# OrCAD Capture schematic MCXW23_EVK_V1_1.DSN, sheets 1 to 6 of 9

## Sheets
1 01_Block diagram: size A3; title: MCXW23-EVK-BB; rev: 1.1; company: NXP Semiconductors; note: MCXW23-EVK-BB; note: 6501 William Cannon Drive West; note: Austin, TX 78735-8598
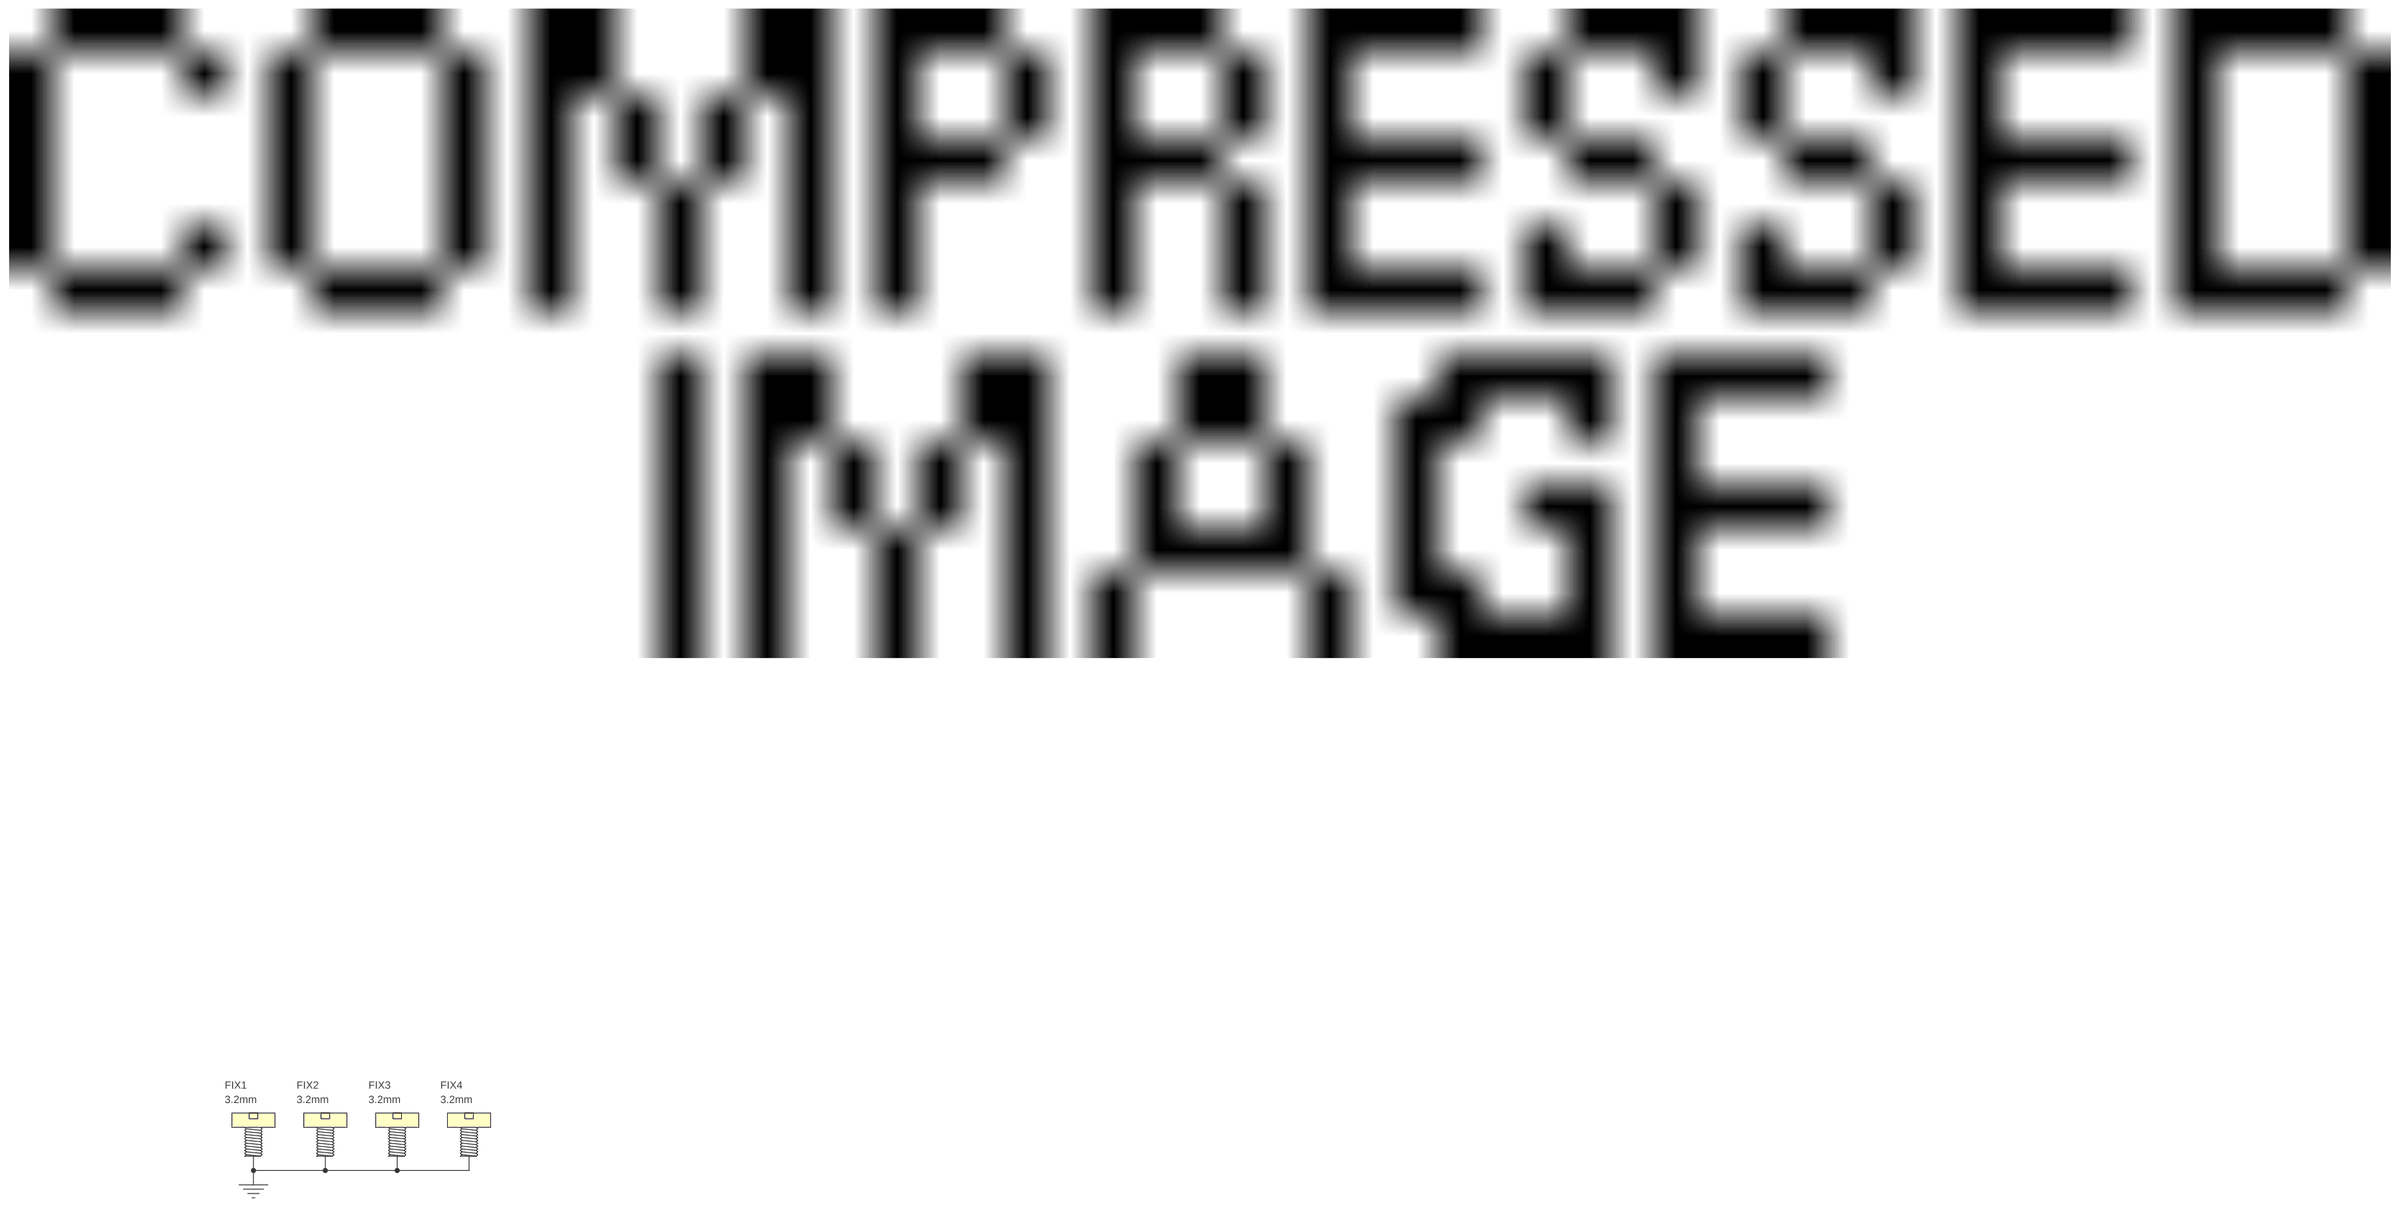
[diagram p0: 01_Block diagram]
2 02_MCXW23xx_RDM: size A3
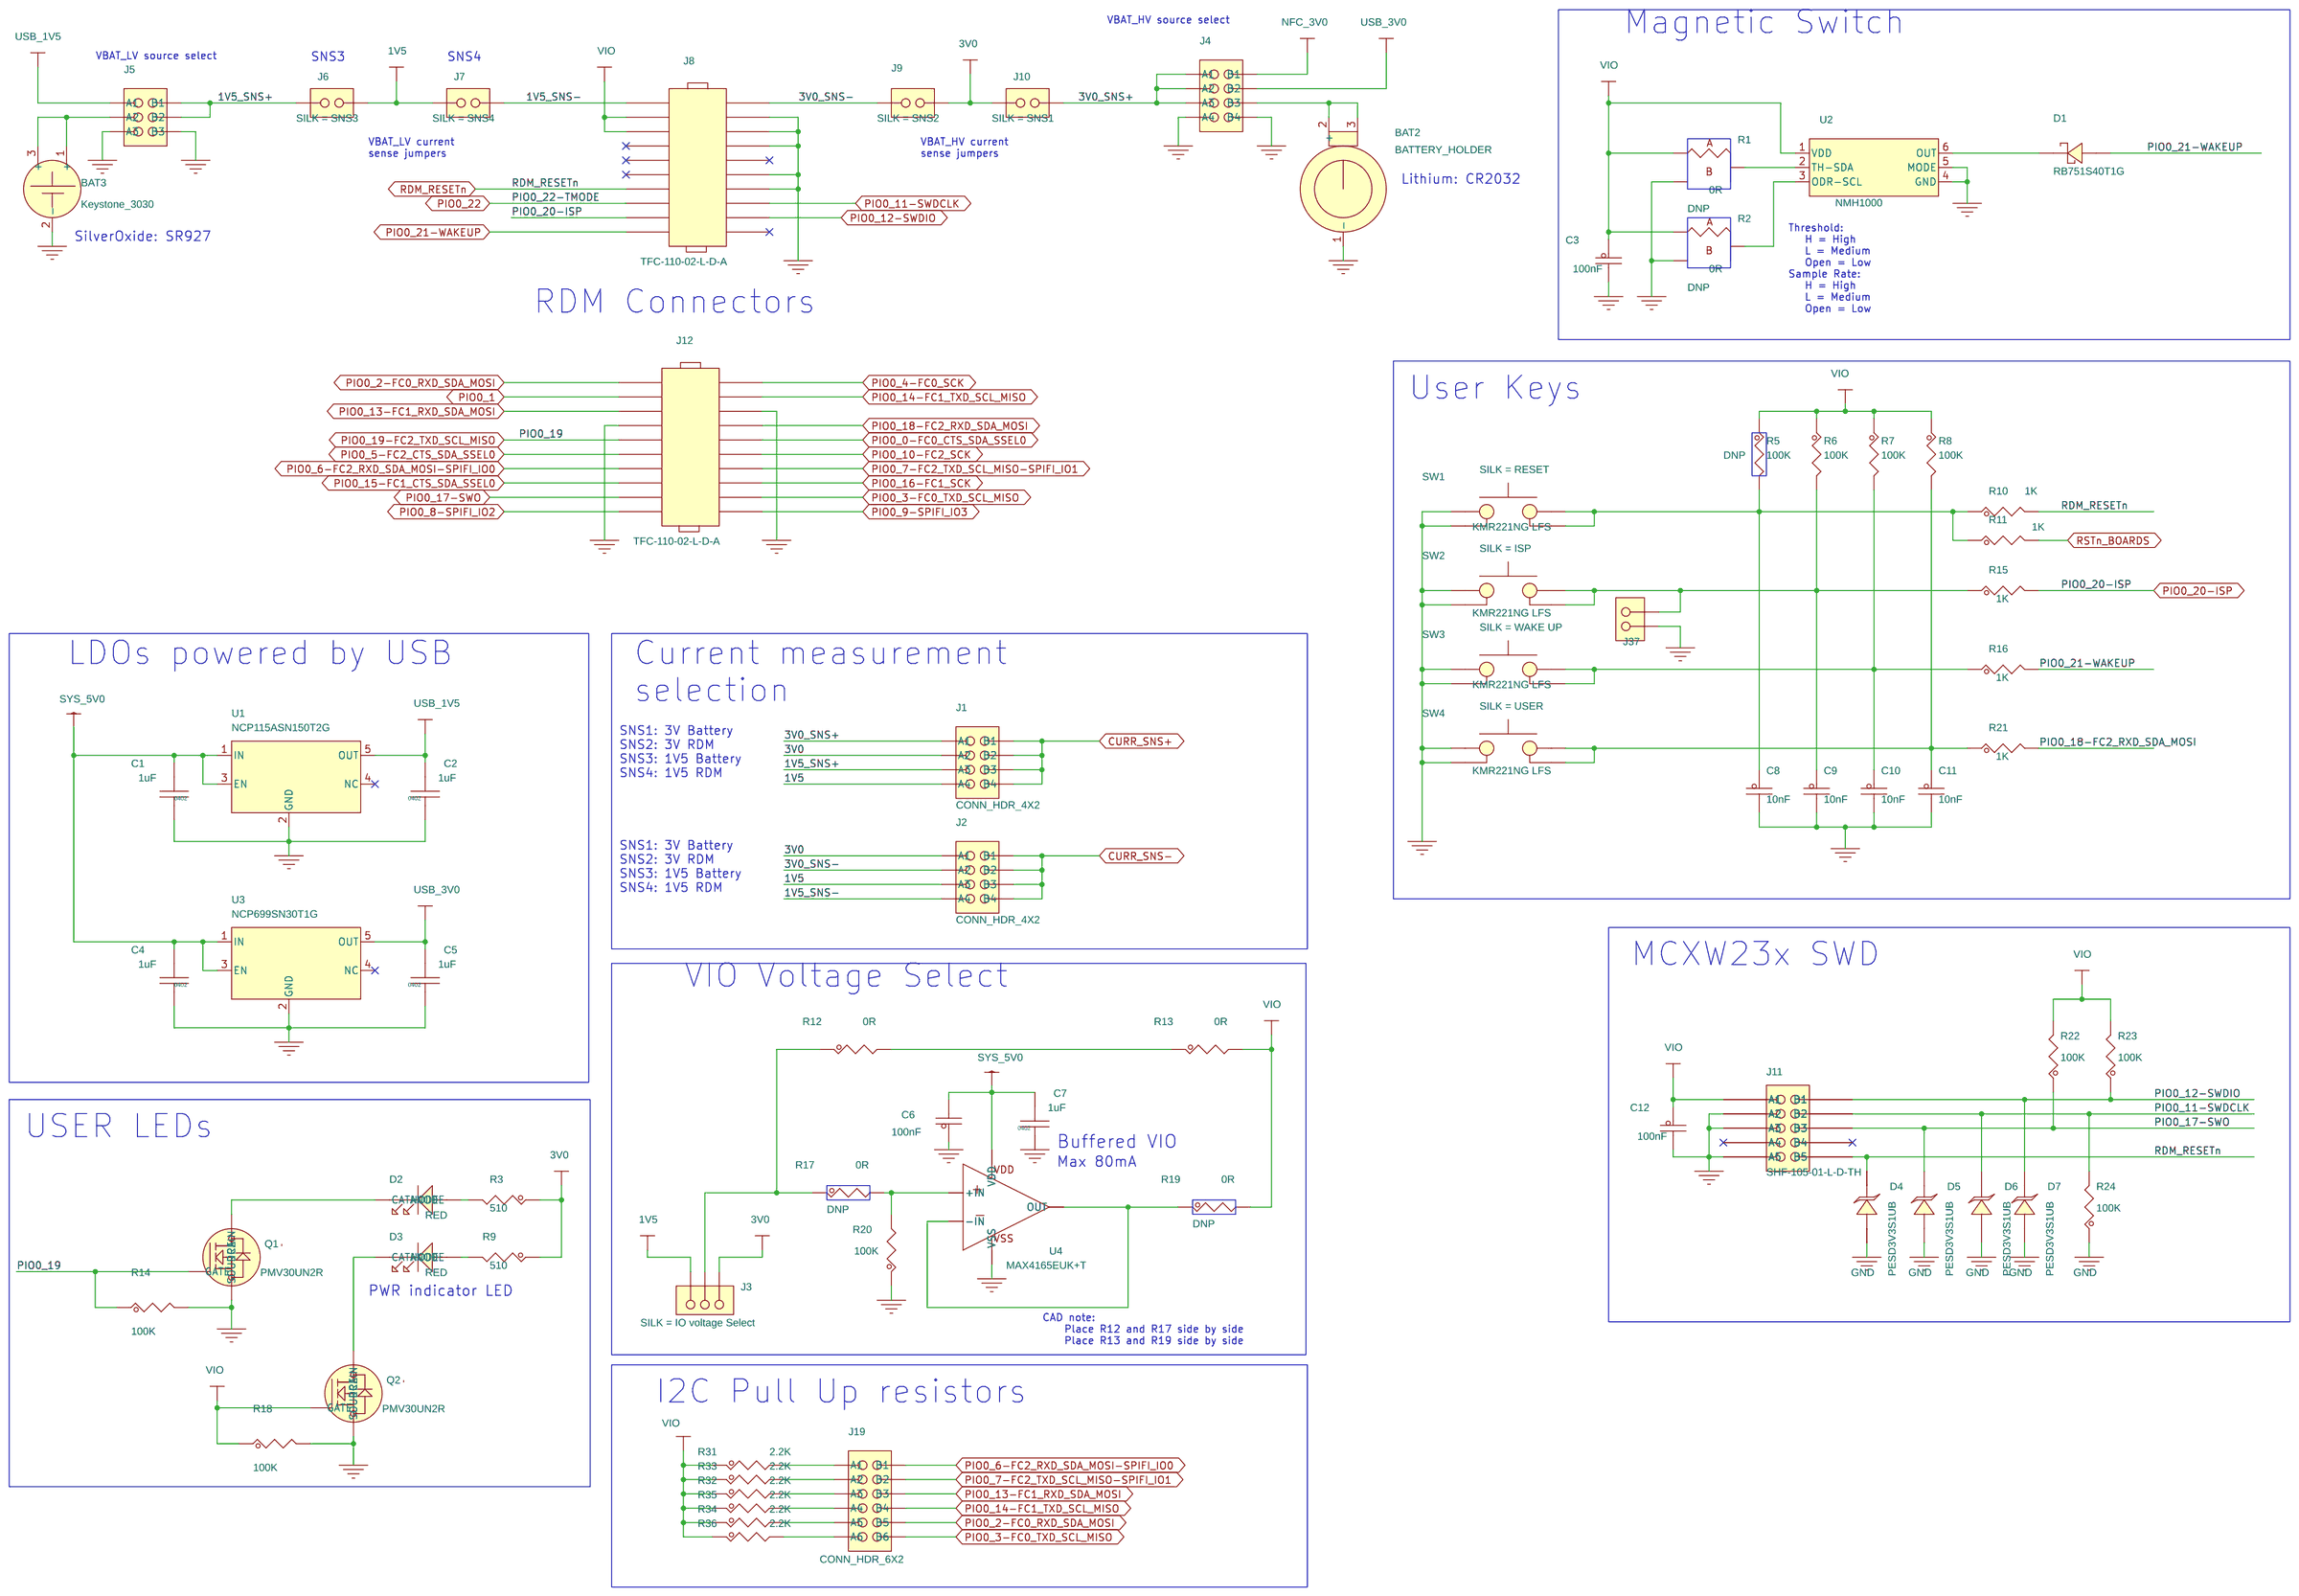
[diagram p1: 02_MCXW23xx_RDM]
3 03_Sensors: size A3
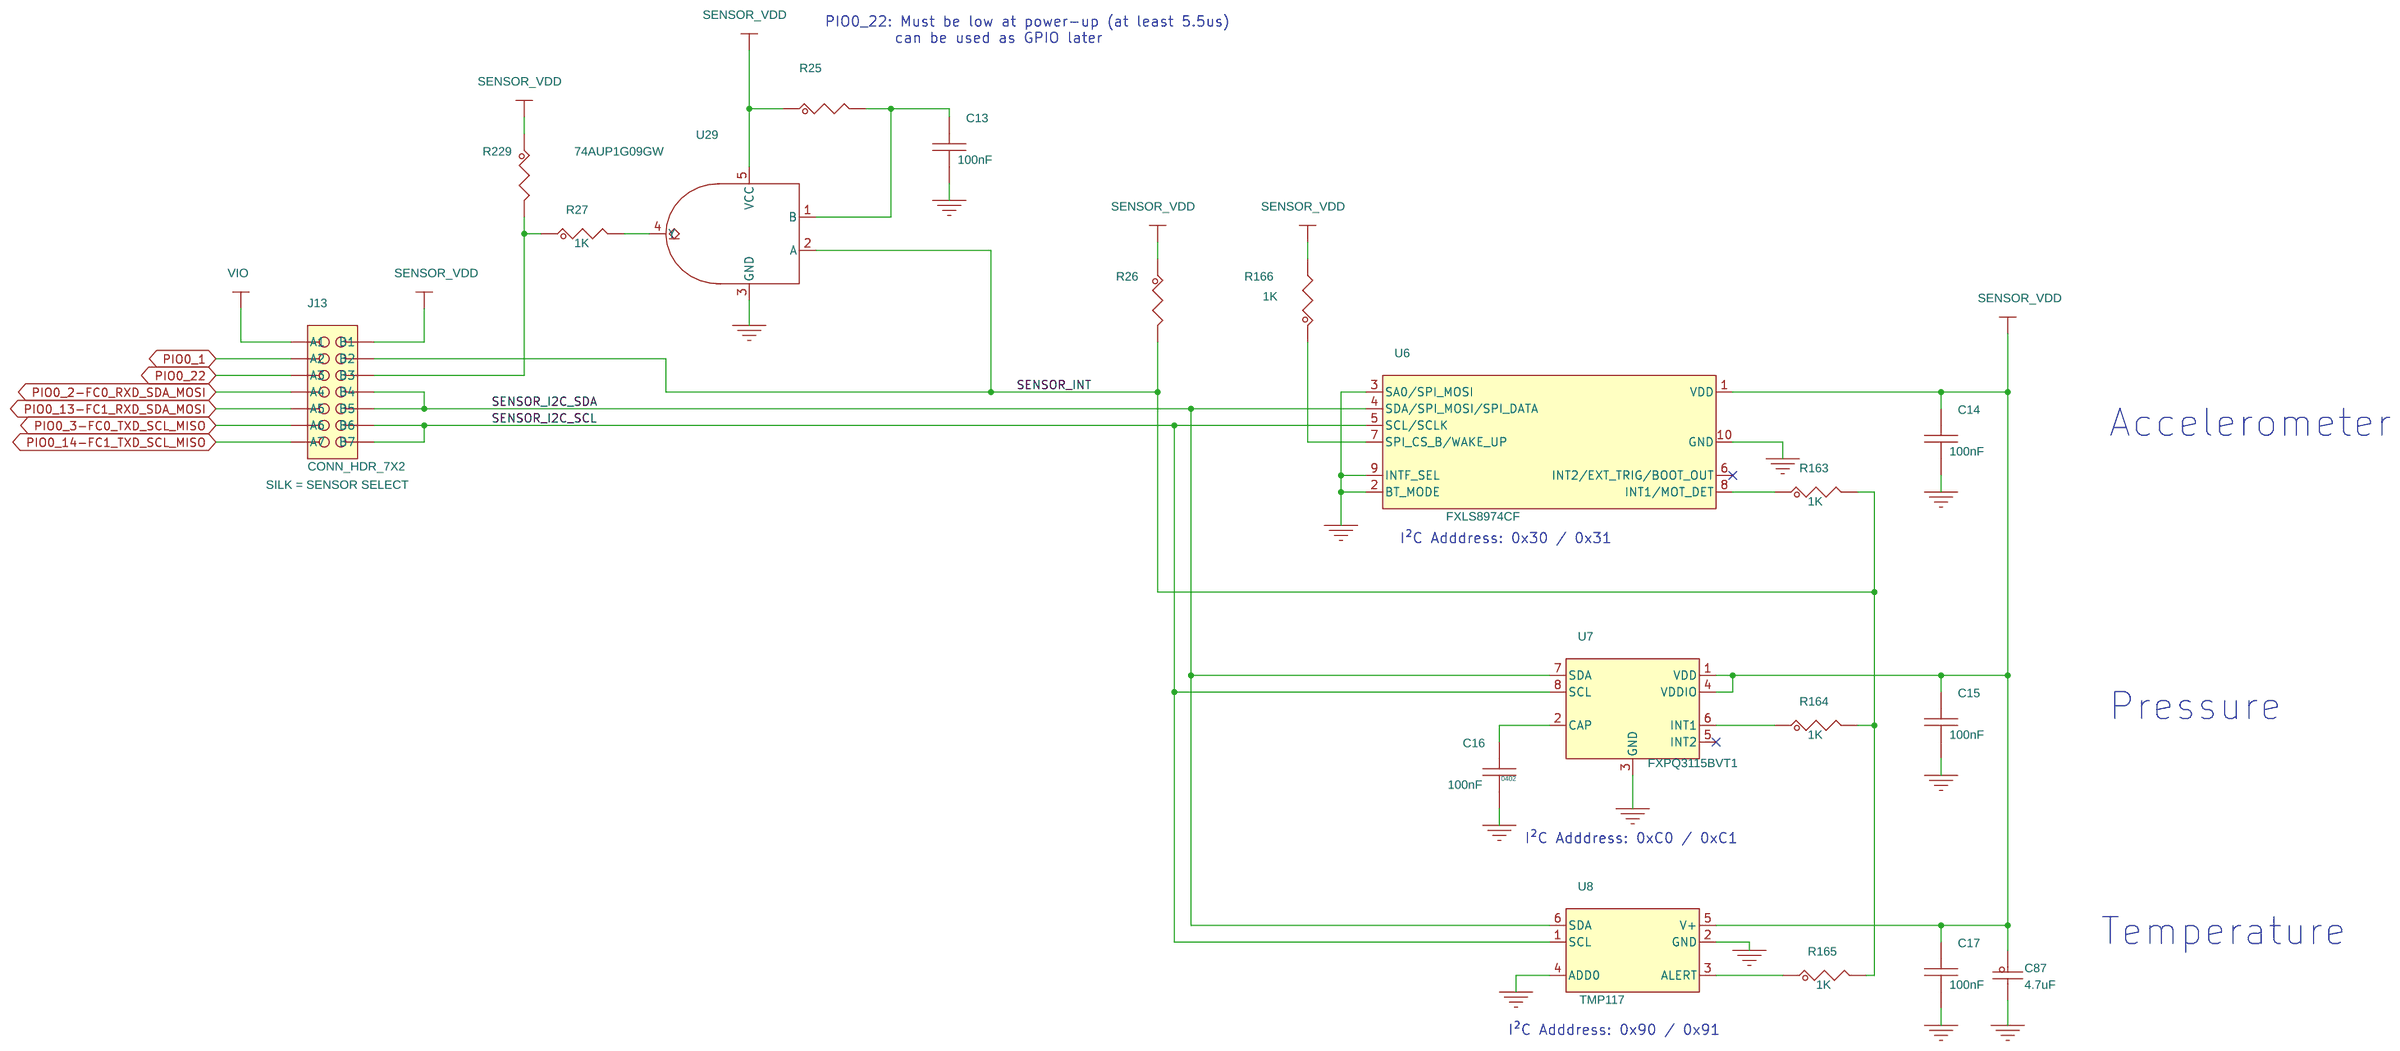
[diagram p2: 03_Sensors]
4 04_MIKRObus_Arduino: size A3
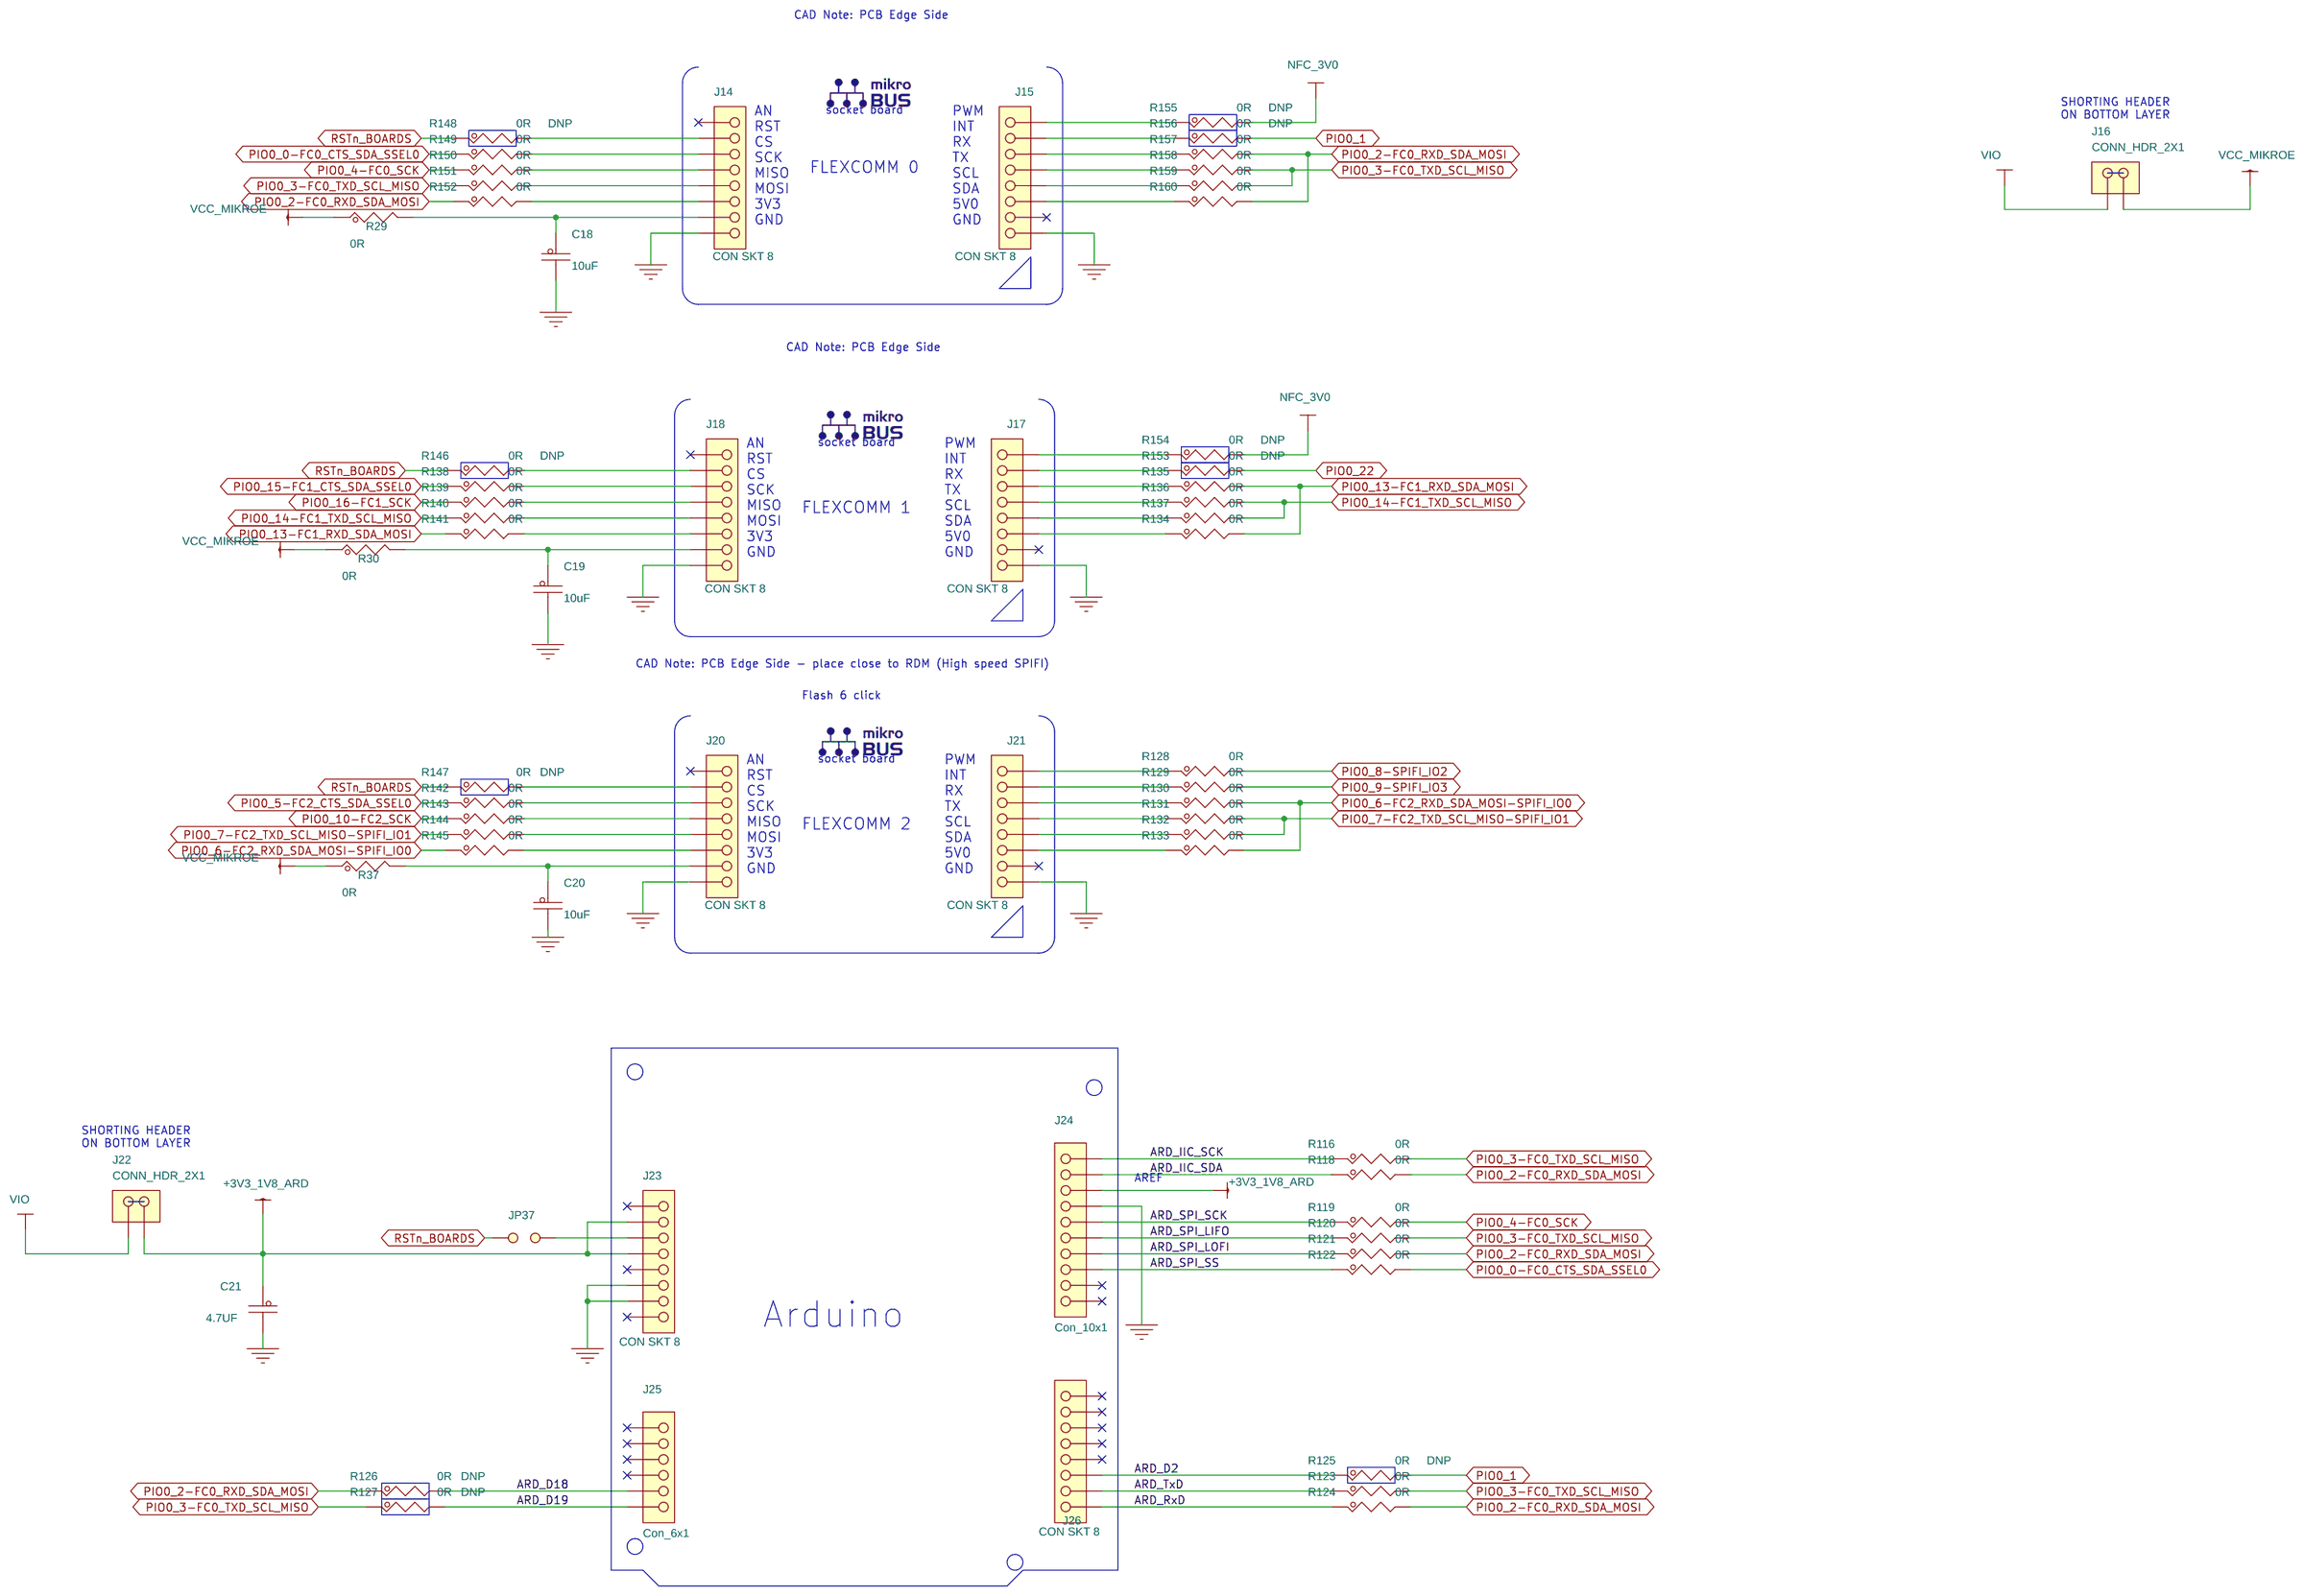
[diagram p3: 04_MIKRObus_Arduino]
5 05_MCU_Link_IO: size A3
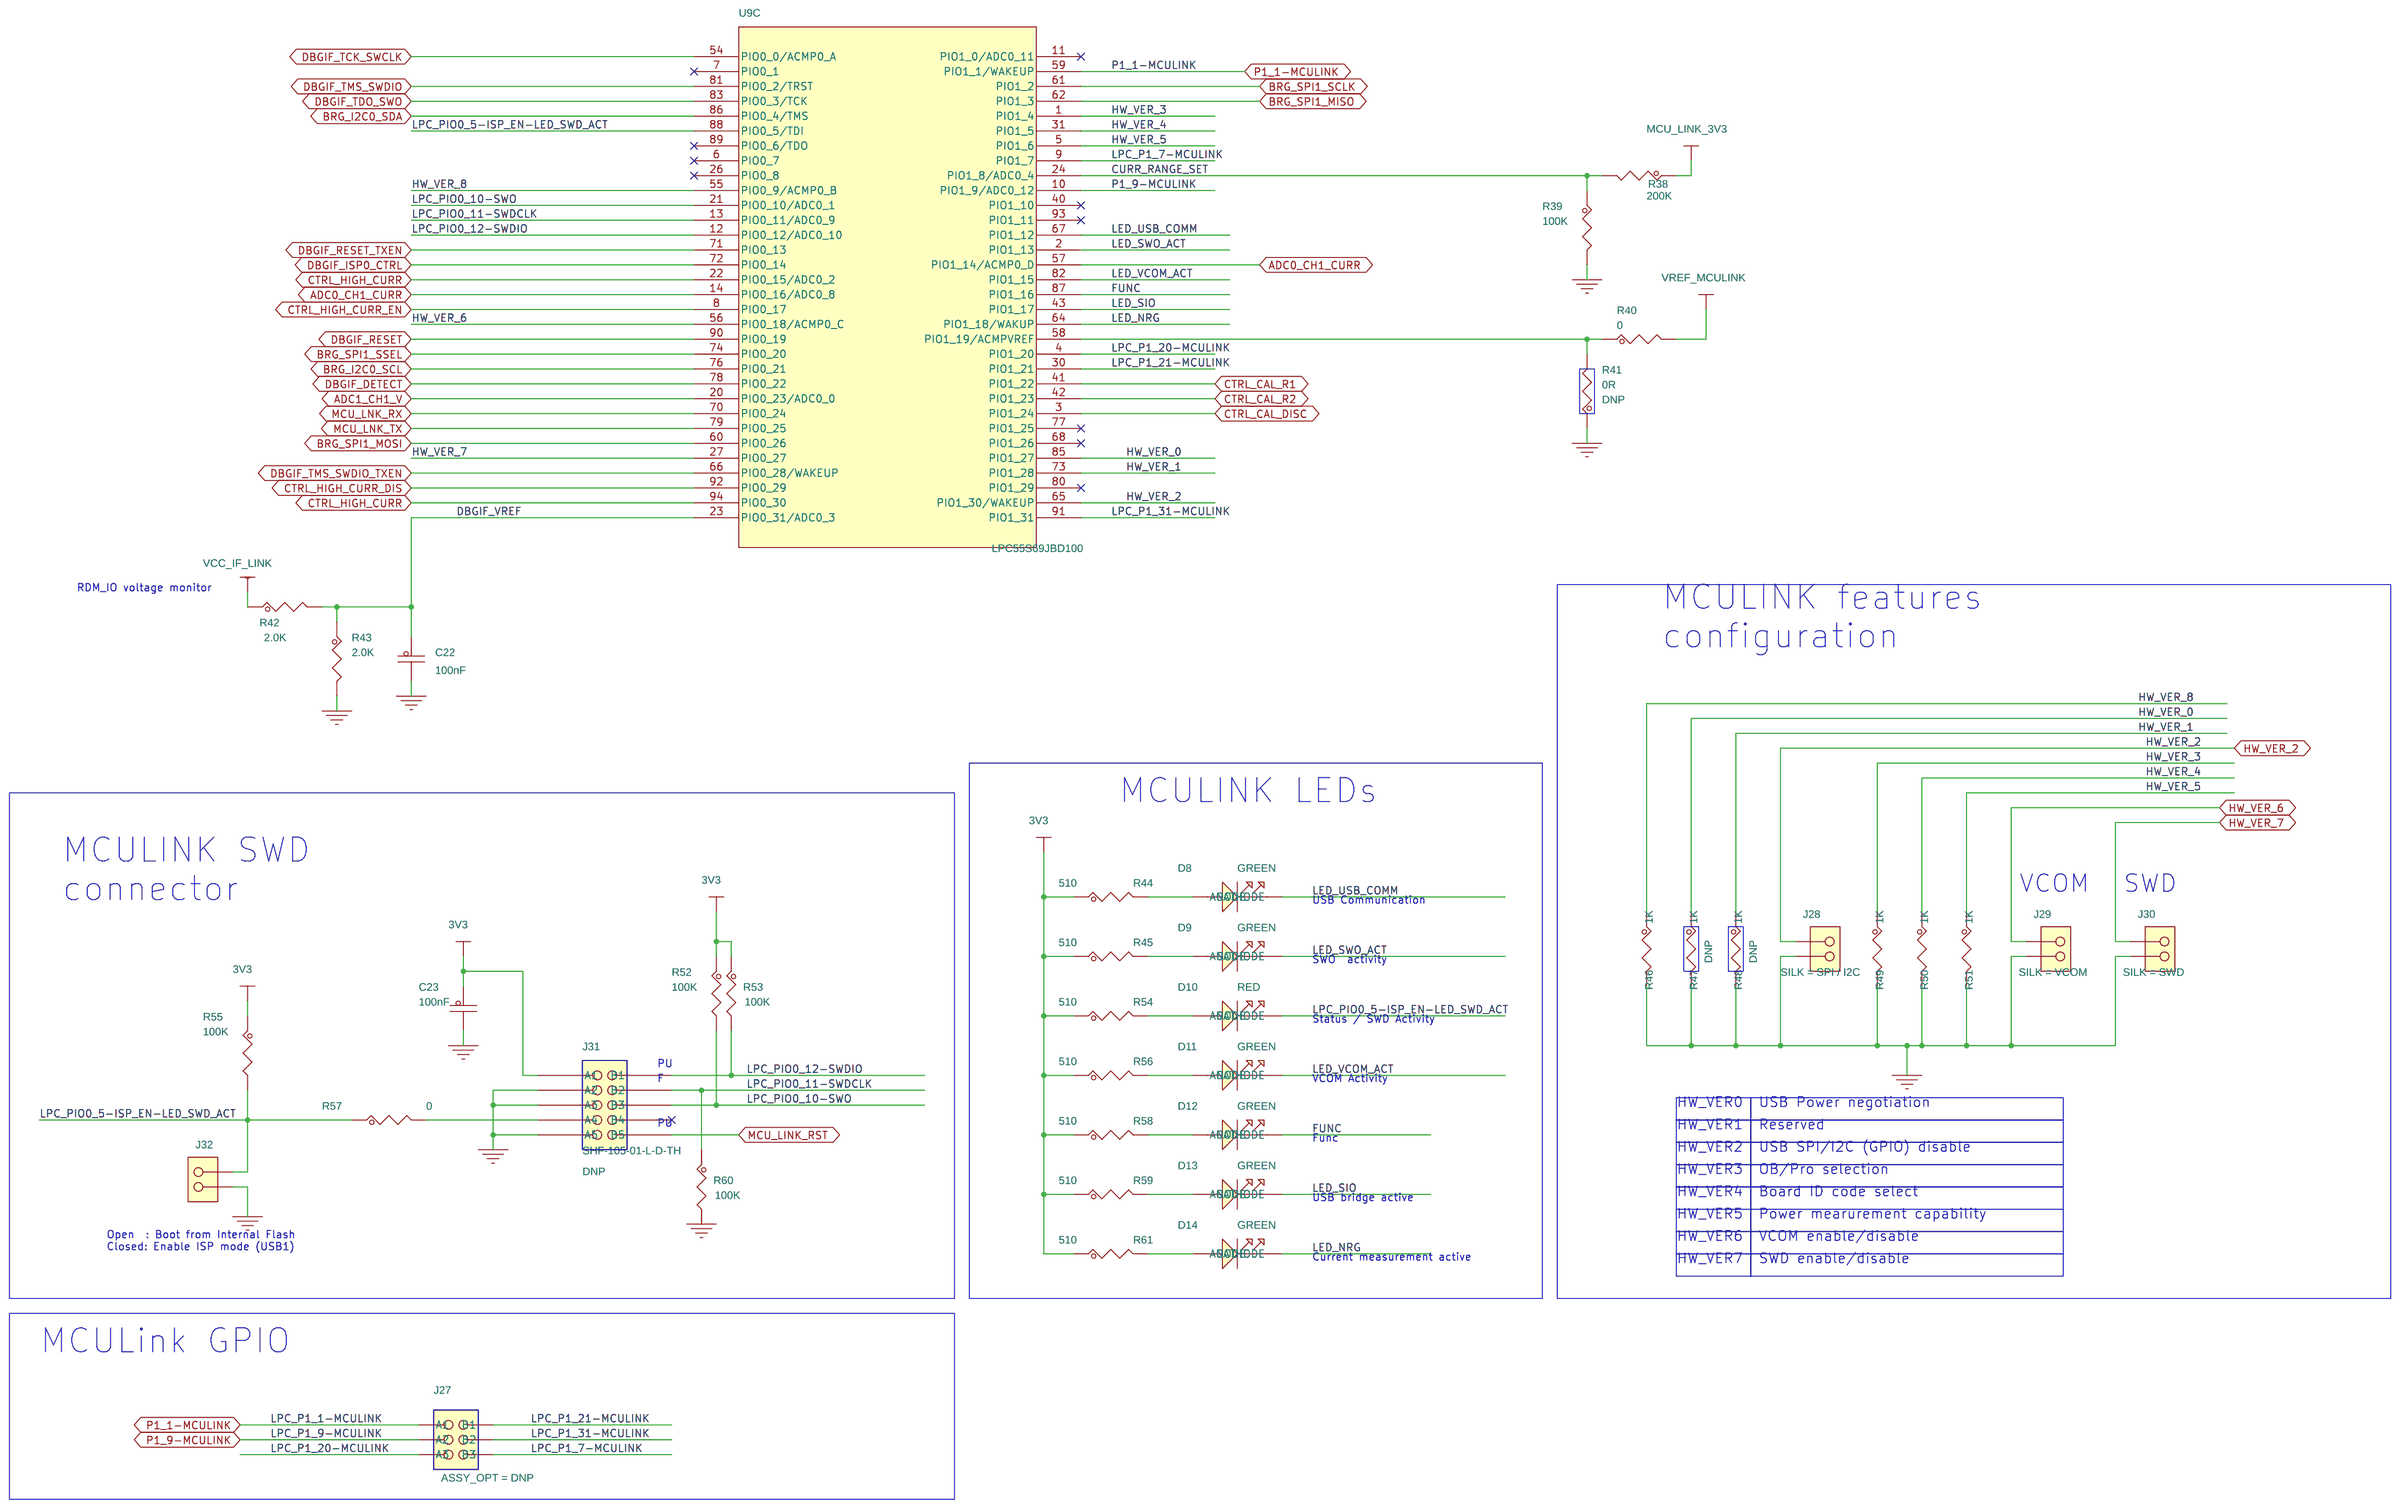
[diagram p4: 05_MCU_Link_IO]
6 06_MCU_link_PWR: size A3
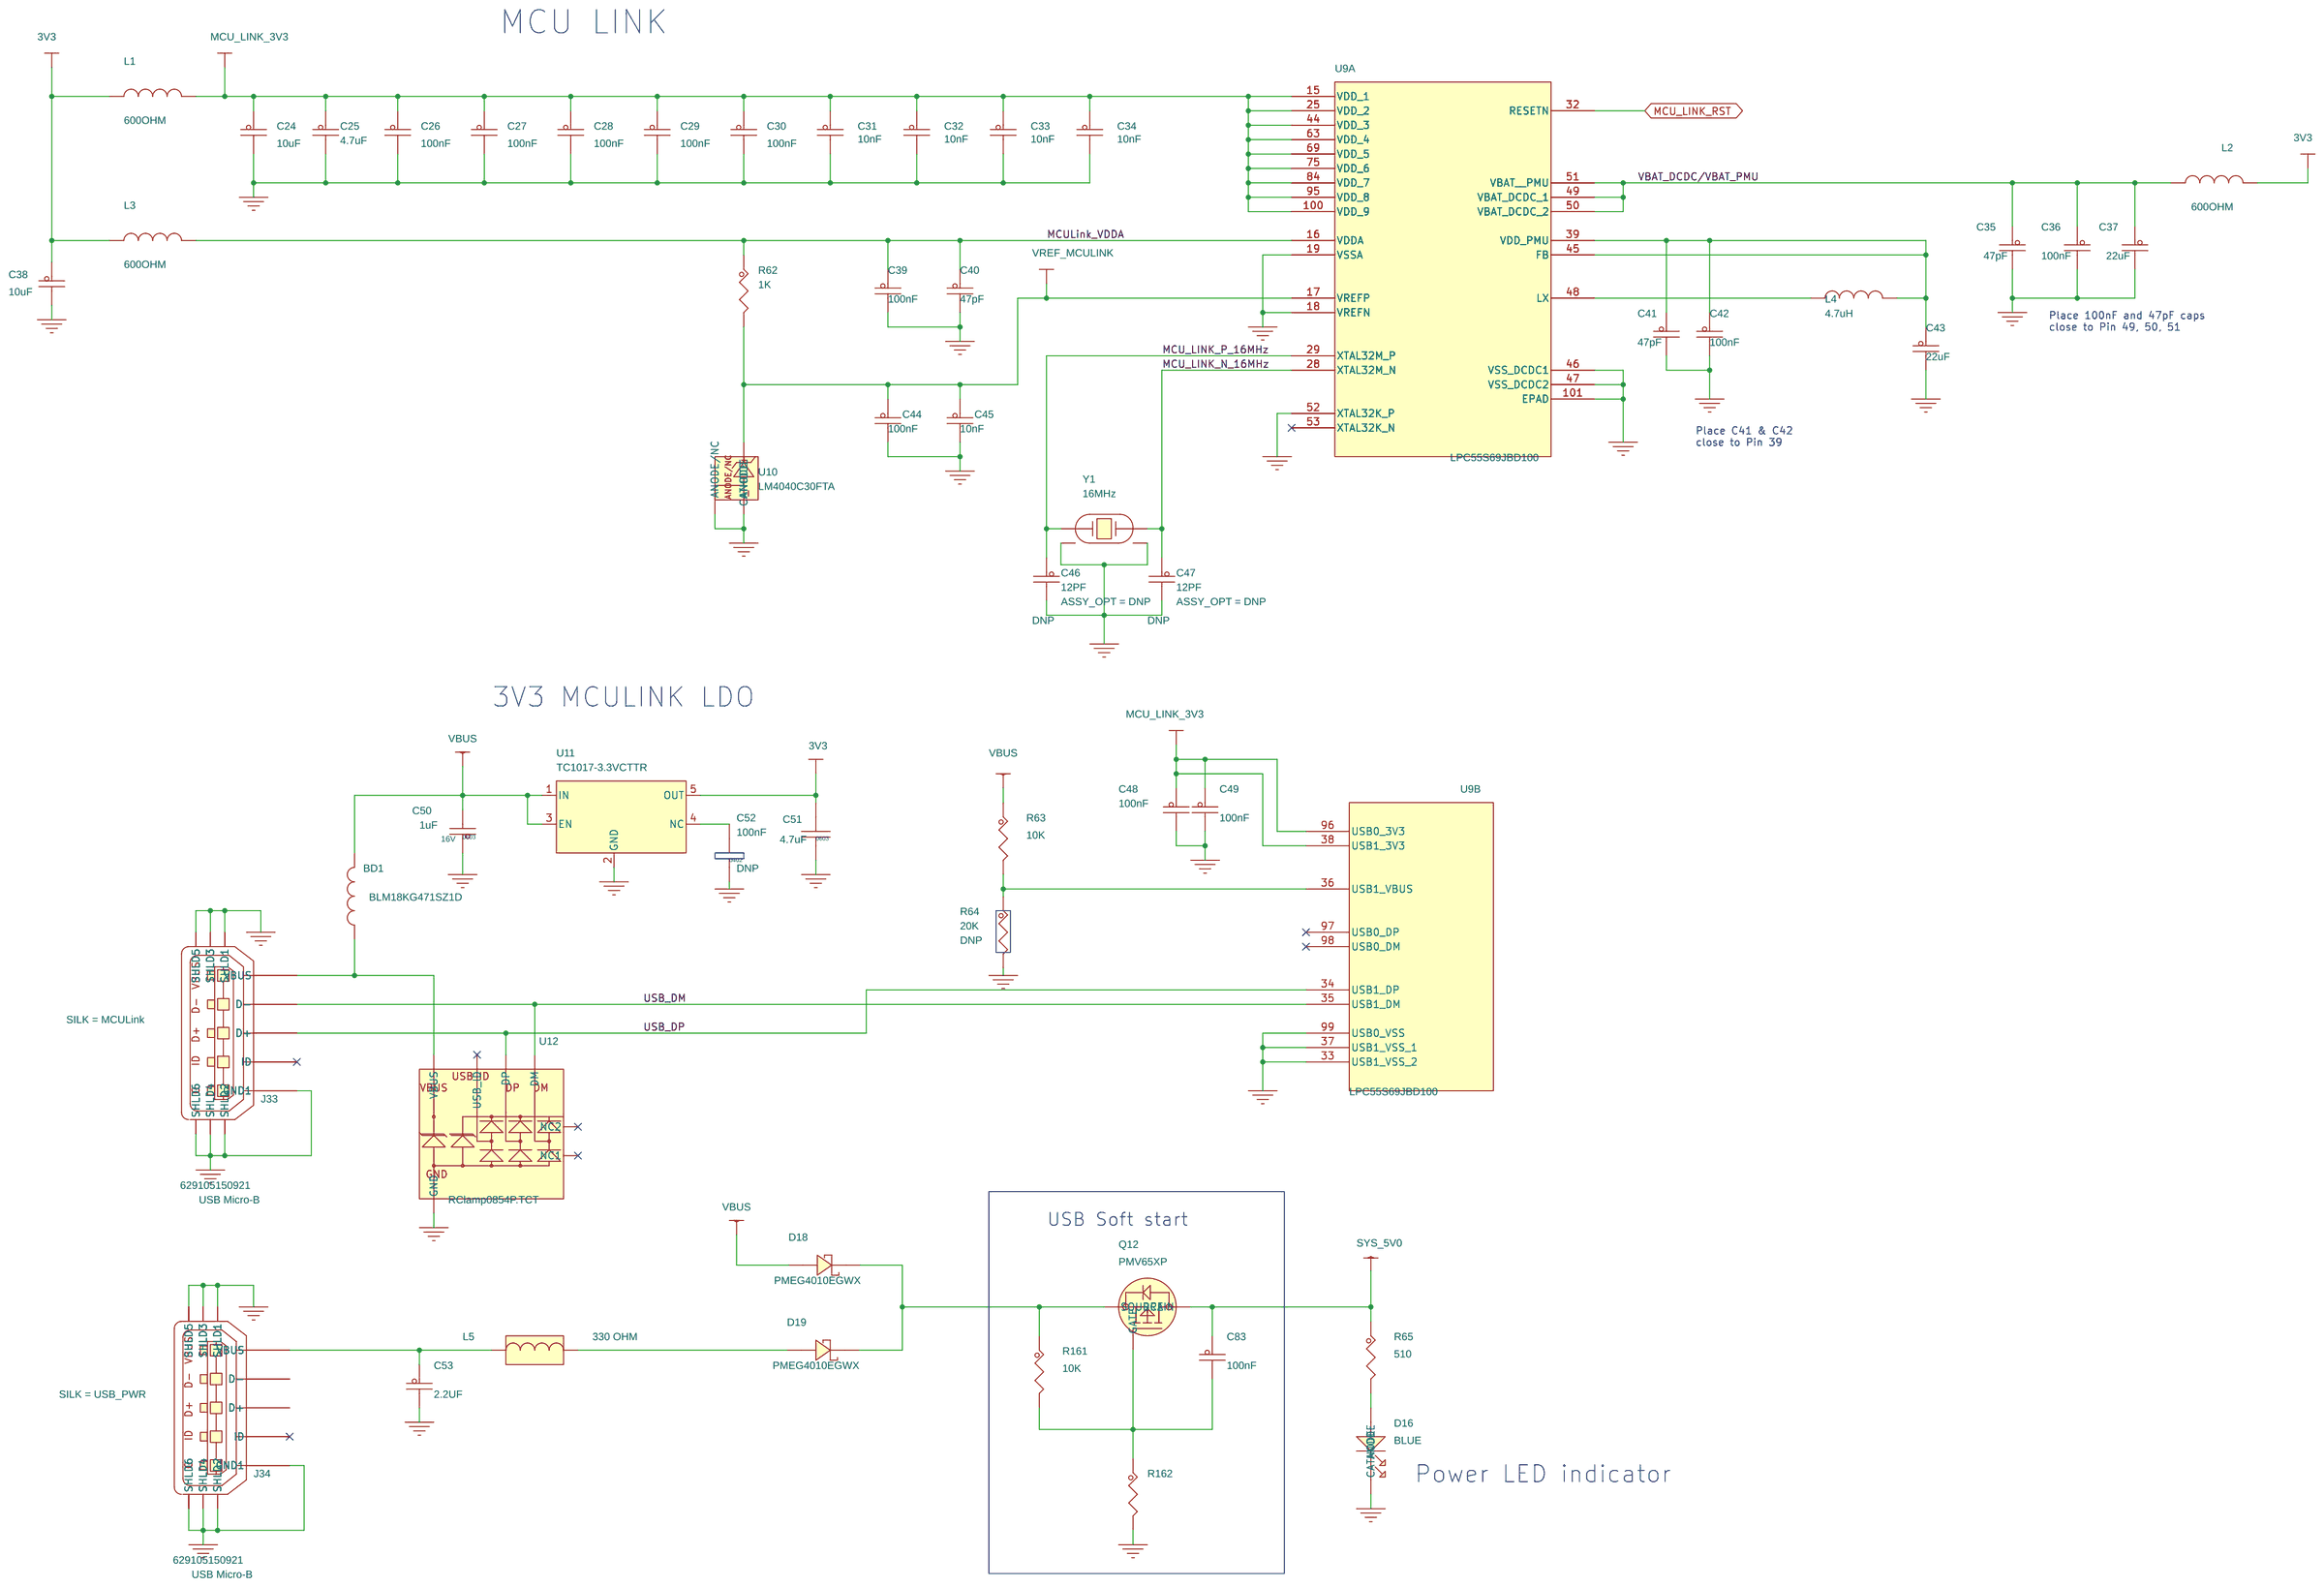
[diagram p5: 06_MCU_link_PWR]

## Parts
sheet 01_Block diagram
FIX1  3.2mm  [fm32_CU70]
FIX2  3.2mm  [fm32_CU70]
FIX3  3.2mm  [fm32_CU70]
FIX4  3.2mm  [fm32_CU70]
sheet 02_MCXW23xx_RDM
BAT2  BATTERY_HOLDER  [renata-hu2032-lf]
BAT3  Keystone_3030  [Keystone-3030]
C1  1uF  [CC0402_25]
C2  1uF  [CC0402_25]
C3  100nF  [CC0402_25]
C4  1uF  [CC0402_25]
C5  1uF  [CC0402_25]
C6  100nF  [CC0402_25]
C7  1uF  [CC0402_25]
C8  10nF  [CC0402_25]
C9  10nF  [CC0402_25]
C10  10nF  [CC0402_25]
C11  10nF  [CC0402_25]
C12  100nF  [CC0402_25]
D1  RB751S40T1G  [SOD523]
D2  RED  [KINGBRIGHT-KP1608]
D3  RED  [KINGBRIGHT-KP1608]
D4  PESD3V3S1UB  [sod523]
D5  PESD3V3S1UB  [sod523]
D6  PESD3V3S1UB  [sod523]
D7  PESD3V3S1UB  [sod523]
J1  CONN_HDR_4X2  [HE14-2X4PTS-MD]
J2  CONN_HDR_4X2  [HE14-2X4PTS-MD]
J3  CONN_HDR_3X1  [HE14-3PTS-MD]
J4  CONN_HDR_4X2  [HE14-2X4PTS-MD]
J5  CONN_HDR_3X2  [HE14-2X3PTS-MD]
J6  CONN_HDR_1X2  [HE14-2X1PTS-MD]
J7  CONN_HDR_1X2  [HE14-2X1PTS-MD]
J8  TFC-110-02-L-D-A  [SAMTEC-TFC-110-02-L-D-A]
J9  CONN_HDR_1X2  [HE14-2X1PTS-MD]
J10  CONN_HDR_1X2  [HE14-2X1PTS-MD]
J11  SHF-105-01-L-D-TH  [SAMTEC-SHF-105-01-L-D-TH]
J12  TFC-110-02-L-D-A  [SAMTEC-TFC-110-02-L-D-A]
J19  CONN_HDR_6X2  [HE14-2X6PTS-MD]
J37  CONN_HDR_2X1  [HE14-2X1PTS-MD]
Q1  PMV30UN2R  [SOT23_GSD]
Q2  PMV30UN2R  [SOT23_GSD]
R1  0R  [R603-X2]
R2  0R  [R603-X2]
R3  510  [RC0402_25]
R5  100K  [RC0402_25]
R6  100K  [RC0402_25]
R7  100K  [RC0402_25]
R8  100K  [RC0402_25]
R9  510  [RC0402_25]
R10  1K  [RC0402_25]
R11  1K  [RC0402_25]
R12  0R  [RC0603_OV]
R13  0R  [RC0603_OV]
R14  100K  [RC0402_25]
R15  1K  [RC0402_25]
R16  1K  [RC0402_25]
R17  0R  [RC0603_OV]
R18  100K  [RC0402_25]
R19  0R  [RC0603_OV]
R20  100K  [RC0402_25]
R21  1K  [RC0402_25]
R22  100K  [RC0402_25]
R23  100K  [RC0402_25]
R24  100K  [RC0402_25]
R31  2.2K  [RC0402_25]
R32  2.2K  [RC0402_25]
R33  2.2K  [RC0402_25]
R34  2.2K  [RC0402_25]
R35  2.2K  [RC0402_25]
R36  2.2K  [RC0402_25]
SW1  KMR221NG LFS  [CK-KMR2]
SW2  KMR221NG LFS  [CK-KMR2]
SW3  KMR221NG LFS  [CK-KMR2]
SW4  KMR221NG LFS  [CK-KMR2]
U1  NCP115ASN150T2G  [TSOP-5]
U2  NMH1000  [VSON6]
U3  NCP699SN30T1G  [TSOP-5]
U4  MAX4165EUK+T  [sot23-5-R]
sheet 03_Sensors
C13  100nF  [CC0402_25]
C14  100nF  [CC0402_25]
C15  100nF  [CC0402_25]
C16  100nF  [CC0402_25]
C17  100nF  [CC0402_25]
C87  4.7uF  [CC0603_OV]
J13  CONN_HDR_7X2  [HE14-2X7PTS-MD]
R25  10K  [RC0603_OV]
R26  10K  [RC0603_OV]
R27  1K  [RC0402_25]
R163  1K  [RC0402_25]
R164  1K  [RC0402_25]
R165  1K  [RC0402_25]
R166  1K  [RC0402_25]
R229  10K  [RC0603_OV]
U6  FXLS8974CF  [DFN10_DF]
U7  FXPQ3115BVT1  [lga8-5x3]
U8  TMP117  [WSON6_DRV]
U29  74AUP1G09GW  [sot353]
sheet 04_MIKRObus_Arduino
C18  10uF  [CC0603_OV]
C19  10uF  [CC0603_OV]
C20  10uF  [CC0603_OV]
C21  4.7UF  [CC0603_OV]
J14  CON SKT 8  [HE14-8PTS-MD]
J15  CON SKT 8  [HE14-8PTS-MD]
J16  CONN_HDR_2X1  [HE14-2X1PTS-MD]
J17  CON SKT 8  [HE14-8PTS-MD]
J18  CON SKT 8  [HE14-8PTS-MD]
J20  CON SKT 8  [HE14-8PTS-MD]
J21  CON SKT 8  [HE14-8PTS-MD]
J22  CONN_HDR_2X1  [HE14-2X1PTS-MD]
J23  CON SKT 8  [HE14-8PTS-MD]
J24  Con_10x1  [HE14-10PTS-MD]
J25  Con_6x1  [HE14-6PTS-MD]
J26  CON SKT 8  [HE14-8PTS-MD]
JP37  Solderjumper  [PST-SD2]
R29  0R  [RC0402_25]
R30  0R  [RC0402_25]
R37  0R  [RC0402_25]
R116  0R  [RC0603_OV]
R118  0R  [RC0603_OV]
R119  0R  [RC0603_OV]
R120  0R  [RC0603_OV]
R121  0R  [RC0603_OV]
R122  0R  [RC0603_OV]
R123  0R  [RC0603_OV]
R124  0R  [RC0603_OV]
R125  0R  [RC0603_OV]
R126  0R  [RC0603_OV]
R127  0R  [RC0603_OV]
R128  0R  [RC0603_OV]
R129  0R  [RC0603_OV]
R130  0R  [RC0603_OV]
R131  0R  [RC0603_OV]
R132  0R  [RC0603_OV]
R133  0R  [RC0603_OV]
R134  0R  [RC0603_OV]
R135  0R  [RC0603_OV]
R136  0R  [RC0603_OV]
R137  0R  [RC0603_OV]
R138  0R  [RC0603_OV]
R139  0R  [RC0603_OV]
R140  0R  [RC0603_OV]
R141  0R  [RC0603_OV]
R142  0R  [RC0603_OV]
R143  0R  [RC0603_OV]
R144  0R  [RC0603_OV]
R145  0R  [RC0603_OV]
R146  0R  [RC0603_OV]
R147  0R  [RC0603_OV]
R148  0R  [RC0603_OV]
R149  0R  [RC0603_OV]
R150  0R  [RC0603_OV]
R151  0R  [RC0603_OV]
R152  0R  [RC0603_OV]
R153  0R  [RC0603_OV]
R154  0R  [RC0603_OV]
R155  0R  [RC0603_OV]
R156  0R  [RC0603_OV]
R157  0R  [RC0603_OV]
R158  0R  [RC0603_OV]
R159  0R  [RC0603_OV]
R160  0R  [RC0603_OV]
sheet 05_MCU_Link_IO
C22  100nF  [CC0402_25]
C23  100nF  [CC0402_25]
D8  GREEN  [KINGBRIGHT-KP1608]
D9  GREEN  [KINGBRIGHT-KP1608]
D10  RED  [KINGBRIGHT-KP1608]
D11  GREEN  [KINGBRIGHT-KP1608]
D12  GREEN  [KINGBRIGHT-KP1608]
D13  GREEN  [KINGBRIGHT-KP1608]
D14  GREEN  [KINGBRIGHT-KP1608]
J27  CONN_HDR_3X2  [HE14-2X3PTS-MD]
J28  CONN_HDR_2X1  [HE14-2X1PTS-MD]
J29  CONN_HDR_2X1  [HE14-2X1PTS-MD]
J30  CONN_HDR_2X1  [HE14-2X1PTS-MD]
J31  SHF-105-01-L-D-TH  [SAMTEC-SHF-105-01-L-D-TH]
J32  CONN_HDR_2X1  [HE14-2X1PTS-MD]
R38  200K  [RC0603_OV]
R39  100K  [RC0402_25]
R40  0  [RC0603_OV]
R41  0R  [RC0603_OV]
R42  2.0K  [RC0603_OV]
R43  2.0K  [RC0603_OV]
R44  510  [RC0402_25]
R45  510  [RC0402_25]
R46  1K  [RC0402_25]
R47  1K  [RC0402_25]
R48  1K  [RC0402_25]
R49  1K  [RC0402_25]
R50  1K  [RC0402_25]
R51  1K  [RC0402_25]
R52  100K  [RC0402_25]
R53  100K  [RC0402_25]
R54  510  [RC0402_25]
R55  100K  [RC0402_25]
R56  510  [RC0402_25]
R57  0  [RC0603_OV]
R58  510  [RC0402_25]
R59  510  [RC0402_25]
R60  100K  [RC0402_25]
R61  510  [RC0402_25]
U9  LPC55S69JBD100  [HLQPF100-14X14]  (sections A,B,C)
sheet 06_MCU_link_PWR
BD1  470 Ohm @ 100MHz  [0603-r]
C24  10uF  [CC0603_OV]
C25  4.7uF  [CC0603_OV]
C26  100nF  [CC0402_25]
C27  100nF  [CC0402_25]
C28  100nF  [CC0402_25]
C29  100nF  [CC0402_25]
C30  100nF  [CC0402_25]
C31  10nF  [CC0402_25]
C32  10nF  [CC0402_25]
C33  10nF  [CC0402_25]
C34  10nF  [CC0402_25]
C35  47pF  [CC0402_25]
C36  100nF  [CC0402_25]
C37  22uF  [CC0603_OV]
C38  10uF  [CC0603_OV]
C39  100nF  [CC0402_25]
C40  47pF  [CC0402_25]
C41  47pF  [CC0402_25]
C42  100nF  [CC0402_25]
C43  22uF  [CC0603_OV]
C44  100nF  [CC0402_25]
C45  10nF  [CC0402_25]
C46  12PF  [CC0402_25]
C47  12PF  [CC0402_25]
C48  100nF  [CC0402_25]
C49  100nF  [CC0402_25]
C50  1uF  [CC0603_OV]
C51  4.7uF  [CC0603_OV]
C52  100nF  [CC0402_25]
C53  2.2UF  [CC0402_25]
C83  100nF  [CC0402_25]
D16  BLUE  [KINGBRIGHT-KP1608]
D18  PMEG4010EGWX  [SOD123]
D19  PMEG4010EGWX  [SOD123]
J33  USB Micro-B  [WE-629_105_150_921]
J34  USB Micro-B  [WE-629_105_150_921]
L1  600OHM  [WE-CBF_0603-HS]
L2  600OHM  [WE-CBF_0603-HS]
L3  600OHM  [WE-CBF_0603-HS]
L4  4.7uH  [MURATA-LQH5BP]
L5  330 OHM  [TDK-MPZ1608]
Q12  PMV65XP  [SOT23_GSD]
R62  1K  [RC0402_25]
R63  10K  [RC0402_25]
R64  20K  [RC0402_25]
R65  510  [RC0402_25]
R161  10K  [RC0402_25]
R162  3k3  [RC0402_25]
U10  LM4040C30FTA  [SOT23-B-R]
U11  TC1017-3.3VCTTR  [SOT23-5-R]
U12  RClamp0854P.TCT  [slp1616p6]
Y1  16MHz  [CX3225CA]

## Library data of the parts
FIX1-FIX4 = FIX
BAT2 = BATTERY_HOLDER_0: Battery Holder, 2032 x 1, Through Hole; Farnell: 1319749; Manufacturer: RENATA; Manufacturer PN: HU2032-LF; Part Number: HU2032-LF; Datasheet: https://www.farnell.com/datasheets/3196466.pdf
BAT3 = Keystone_3030: Distributor: Digi-Key; Distributor PN: 36-3030-ND; Manufacturer: Keystone; Manufacturer PN: 3030
C1 C2 C4 C5 C7 = CAPACITOR__0: CAP CER 1UF 10V X5R 0402; Distributor: Digi-Key; Distributor PN: 490-3890-1-ND; Manufacturer: Murata Electronics North America; Manufacturer PN: GRM155R61A105KE15D; PUISS/VOLT: 10V; TOLERANCE: +/-10%; TYPE: 0402; Datasheet: http://www.murata.com/~/media/webrenewal/support/library/catalog/products/capacitor/mlcc/c02e.pdf
C3 C6 C12 = CAP_NP: CAP CER 0.1UF 25V X7R 0402; FPLIST: CC0402_25,CC0402_HD,0402_CC; HEIGHT: 0.55MM; MFG_NAME01: TDK; MFG_PN01: CGA2B3X7R1E104K050BB; Manufacturer: TDK; Manufacturer PN: CGA2B3X7R1E104K050BB; Package Size: 0402; Package Type: SMD; ROHS: Yes; Tolerance: 10%; VOLTAGE: 25V
C8-C11 C31-C34 C45 = CAP_NP: CAP CER 0.01UF 16V 20% X7R 0402; FPLIST: CC0402_25,CC0402_HD,0402_CC; HEIGHT: 0.56MM; MFG_NAME01: AVX; MFG_PN01: 0402YC103MAT2A; Manufacturer: AVX; Manufacturer PN: 0402YC103MAT2A; Package Size: 0402; ROHS: Yes; Tolerance: 20%; VOLTAGE: 16V
D1 = DIODE_SCHTKY: Small Signal Schottky Diode, Single, 30 V, 30 mA, 370 mV, 500 mA, 150 °C; Farnell: 2317437; MFG_NAME01: ONSEMI; Manufacturer: ONSEMI; ROHS: Yes; VOLTAGE: 40V
D2 = LED: LED, Red, SMD, 0603 [1608 Metric], 30 mA, 2 V, 625 nm; Farnell: 2322071; HEIGHT: 0.85MM; MFG_NAME01: WURTH ELEKTRONIK; MFG_PN01: 150060RS75000; Manufacturer: WURTH ELEKTRONIK / WURTH ELEKTRONIK / WURTH ELEKTRONIK; Manufacturer PN: 150060RS75000; ROHS: Yes
D3 = LED: LED, Red, SMD, 0603 [1608 Metric], 30 mA, 2 V, 625 nm; Farnell: 2322071; HEIGHT: 0.85MM; MFG_NAME01: WURTH ELEKTRONIK; MFG_PN01: 150060RS75000; Manufacturer: WURTH ELEKTRONIK; Manufacturer PN: 150060RS75000; ROHS: Yes
D4-D7 = DIODE_TVS: DIODE TVS UNIDIR 3.3VWM 20VC SOD523; Farnell: 8737568; HEIGHT: 0.65MM; MFG_NAME01: NEXPERIA; MFG_PN01: PESD3V3S1UB,115; Manufacturer: NEXPERIA; Manufacturer PN: PESD3V3S1UB,115; REQUESTED_COMPLETION_DATE: Not an expedite request; ROHS: Yes
J1 J2 J4 = CONN_HDR_4X2: Pin Header, Board-to-Board, 2.54 mm, 2 Rows, 8 Contacts, Through Hole, AMPMODU II; Farnell: 3398641; MFG_NAME01: AMP - TE CONNECTIVITY; MFG_PN01: 826656-4; Manufacturer: AMP - TE CONNECTIVITY; Manufacturer PN: 826656-4
J3 = CONN_HDR_3X1: Pin Header, Unshrouded, Board-to-Board, 2.54 mm, 1 Rows, 3 Contacts, Through Hole, TSW; Farnell: 2505045; MFG_NAME01: Pin Header, Unshrouded, Board-to-Board, 2.54 mm, 1 Rows, 3 Contacts, Through Hole, TSW; MFG_PN01: TSW-103-07-G-S; Manufacturer: Pin Header, Unshrouded, Board-to-Board, 2.54 mm, 1 Rows, 3 Contacts, Through Hole, TSW; Manufacturer PN: TSW-103-07-G-S; SILK: IO voltage Select
J5 = CONN_HDR_3X2: Pin Header, Board-to-Board, 2.54 mm, 2 Rows, 6 Contacts, Through Hole; Farnell: 3398639; MFG_NAME01: AMP - TE CONNECTIVITY; MFG_PN01: 826656-3; Manufacturer: AMP - TE CONNECTIVITY; Manufacturer PN: 826656-3
J6 = CONN_HDR_1X2: Pin Header, Unshrouded, Board-to-Board, 2.54 mm, 1 Rows, 2 Contacts, Through Hole, TSW; Farnell: 2505044; MFG_NAME01: Samtec; MFG_PN01: TSW-102-07-G-S; Manufacturer: Samtec; Manufacturer PN: TSW-102-07-G-S; SILK: SNS3
J7 = CONN_HDR_1X2: Pin Header, Unshrouded, Board-to-Board, 2.54 mm, 1 Rows, 2 Contacts, Through Hole, TSW; Farnell: 2505044; MFG_NAME01: Samtec; MFG_PN01: TSW-102-07-G-S; Manufacturer: Samtec; Manufacturer PN: TSW-102-07-G-S; SILK: SNS4
J8 J12 = HEADER_10X2: Pin Header, Board-to-Board, Wire-to-Board, 1.27 mm, 2 Rows, 20 Contacts, Surface Mount; Farnell: 3515051; Manufacturer: Samtec; Datasheet: https://www.farnell.com/datasheets/1927722.pdf
J9 = CONN_HDR_1X2: Pin Header, Unshrouded, Board-to-Board, 2.54 mm, 1 Rows, 2 Contacts, Through Hole, TSW; Farnell: 2505044; MFG_NAME01: Samtec; MFG_PN01: TSW-102-07-G-S; Manufacturer: Samtec; Manufacturer PN: TSW-102-07-G-S; SILK: SNS2
J10 = CONN_HDR_1X2: Pin Header, Unshrouded, Board-to-Board, 2.54 mm, 1 Rows, 2 Contacts, Through Hole, TSW; Farnell: 2505044; MFG_NAME01: Samtec; MFG_PN01: TSW-102-07-G-S; Manufacturer: Samtec; Manufacturer PN: TSW-102-07-G-S; SILK: SNS1
J11 = CONN_HDR_5X2: Pin Header, Wire-to-Board, 1.27 mm, 2 Rows, 10 Contacts, Through Hole, SHF Series; Farnell: 2308450; HEIGHT: 5.33mm; Jumper (Default): OPEN; MFG_NAME01: Samtec; Manufacturer: Samtec; ROHS: Yes; Temp Range: -55DegC to +105DegC; Temp_Range: -55DegC to +105DegC; Datasheet: https://www.farnell.com/datasheets/1927736.pdf
J19 = CONN_HDR_6X2
J32 J37 = CONN_HDR_2X1
Q1 Q2 = MOSFET_N_0: Power MOSFET, N Channel, 20 V, 5.4 A, 0.024 ohm, SOT-23, Surface Mount; Farnell: 2469652; HEIGHT: 3.0MM; MFG_NAME01: NEXPERIA; Manufacturer: NEXPERIA; ROHS: Yes; Temp Range: -65°C ~ 150°C; Temp_Range: -65°C ~ 150°C; VOLTAGE: 20V
R1 R2 = RES_3PIN: RES MF ZERO OHM 1/10W -- 0603; ASSY_OPT: DNP; Assembly Option: DNP; FPLIST: RC0603_OV,RC0603,R603-X2,0603_CC,IND_0603HP_NSP,CC0603_OV_NSP; HEIGHT: 0.6MM; Jumper (Default): 1-2; MFG_NAME01: YAGEO AMERICA; MFG_PN01: RC0603FR-070RL; Manufacturer: YAGEO AMERICA; Manufacturer PN: RC0603FR-070RL; ROHS: Yes; Temp Range: –55 °C to +155 °C; Temp_Range: –55 °C to +155 °C
R3 R9 = RES: RES 510 OHMS 1/16W 5% RC0402 ROHS; FPLIST: RC0402_25,RC0402_HD,0402_CC; HEIGHT: 0.4 MM; MFG_NAME01: YAGEO AMERICA; MFG_PN01: RC0402JR-07510RL; Manufacturer: YAGEO AMERICA; Manufacturer PN: RC0402JR-07510RL; ROHS: Yes; Temp_Range: -55C to +155C
R5 = RES: RES MF 100K 1/16W 1% 0402; ASSY_OPT: DNP; Assembly Option: DNP; FPLIST: RC0402_25,RC0402_HD,0402_CC; HEIGHT: 0.4MM; MFG_NAME01: NIC COMPONENTS CORP; MFG_PN01: NRCL04F1003TRF; Manufacturer: NIC COMPONENTS CORP; Manufacturer PN: NRCL04F1003TRF; ROHS: Yes; Tolerance: 1%
R6-R8 R14 R18 R20 R22-R24 = RES: RES MF 100K 1/16W 1% 0402; FPLIST: RC0402_25,RC0402_HD,0402_CC; HEIGHT: 0.4MM; MFG_NAME01: NIC COMPONENTS CORP; MFG_PN01: NRCL04F1003TRF; Manufacturer: NIC COMPONENTS CORP; Manufacturer PN: NRCL04F1003TRF; ROHS: Yes; Tolerance: 1%
R10 R11 R15 R16 R21 R163-R166 = RES: RES MF 1.0K 1/16W 5% 0402; FPLIST: RC0402_25,RC0402_HD,RC0402_X2,0402_CC; HEIGHT: 0.4MM; MFG_NAME01: NIC COMPONENTS CORP; MFG_PN01: NRCL04J102TRF; Manufacturer: NIC COMPONENTS CORP; Manufacturer PN: NRCL04J102TRF; ROHS: Yes; Temp Range: -55°C to +155°C; Temp_Range: -55°C to +155°C; Tolerance: 5%
R12 R13 R116 R118-R124 R128-R145 R149-R152 R157-R160 = RES: RES MF ZERO OHM 1/10W -- 0603; FPLIST: RC0603_OV,RC0603,R603-X2,0603_CC; HEIGHT: 0.6MM; MFG_NAME01: YAGEO AMERICA; MFG_PN01: RC0603FR-070RL; Manufacturer: YAGEO AMERICA; Manufacturer PN: RC0603FR-070RL; ROHS: Yes; Temp Range: –55 °C to +155 °C
R17 R19 R125-R127 R146-R148 R153-R156 = RES: RES MF ZERO OHM 1/10W -- 0603; ASSY_OPT: DNP; Assembly Option: DNP; FPLIST: RC0603_OV,RC0603,R603-X2,0603_CC; HEIGHT: 0.6MM; MFG_NAME01: YAGEO AMERICA; MFG_PN01: RC0603FR-070RL; Manufacturer: YAGEO AMERICA; Manufacturer PN: RC0603FR-070RL; ROHS: Yes; Temp Range: –55 °C to +155 °C
R31-R36 = RES: RES MF 2.2K 1/16W 1% 0402; AGILE_PN: 470-78359; CAD_APPROVED: Yes; FPLIST: RC0402_25,RC0402_HD,0402_CC; HEIGHT: 0.4MM; MFG_NAME01: WALSIN TECHNOLOGY CORP.; MFG_PN01: WR04X2201FTL; Manufacturer: WALSIN TECHNOLOGY CORP.; Manufacturer PN: WR04X2201FTL; ROHS: Yes; Temp Range: -55C to +155C; Temp_Range: -55C to +155C; Tolerance: 1%
SW1 = SW_PB_0: SW SPST MOM PB NO 50MA 32V SMT; Farnell: 2845727; HEIGHT: 1.9 MM; MFG_NAME01: C&K COMPONENTS; Manufacturer: C&K COMPONENTS; ROHS: Yes; SILK: RESET; Temp Range: -40° C to +85° C; Temp_Range: -40° C to +85° C; VOLTAGE: 32V
SW2 = SW_PB_0: SW SPST MOM PB NO 50MA 32V SMT; Farnell: 2845727; HEIGHT: 1.9 MM; MFG_NAME01: C&K COMPONENTS; Manufacturer: C&K COMPONENTS; ROHS: Yes; SILK: ISP; Temp Range: -40° C to +85° C; Temp_Range: -40° C to +85° C; VOLTAGE: 32V
SW3 = SW_PB_0: SW SPST MOM PB NO 50MA 32V SMT; Farnell: 2845727; HEIGHT: 1.9 MM; MFG_NAME01: C&K COMPONENTS; Manufacturer: C&K COMPONENTS; ROHS: Yes; SILK: WAKE UP; Temp Range: -40° C to +85° C; Temp_Range: -40° C to +85° C; VOLTAGE: 32V
SW4 = SW_PB_0: SW SPST MOM PB NO 50MA 32V SMT; Farnell: 2845727; HEIGHT: 1.9 MM; MFG_NAME01: C&K COMPONENTS; Manufacturer: C&K COMPONENTS; ROHS: Yes; SILK: USER; Temp Range: -40° C to +85° C; Temp_Range: -40° C to +85° C; VOLTAGE: 32V
U1 = TPS76930_1: Fixed LDO Voltage Regulator, 1.7V to 5.5V, 1.5V/300mA out, TSOP-5; Distributor: Digi-Key; Farnell: 2981134; Manufacturer: OnSemi; STUFFING: YES; Datasheet: http://www.farnell.com/datasheets/2711386.pdf
U2 = NMH1000: Manufacturer: NXP
U3 = TPS76930_1: Fixed LDO Voltage Regulator, 2.1V to 6V In, 340mV Dropout, 3V/300mA Out, TSOP-5; Distributor: Digi-Key; Farnell: 2534216; Manufacturer: OnSemi; STUFFING: YES; Datasheet: https://www.farnell.com/datasheets/194854.pdf
U4 = OPAMP_SGL_5P: Operational Amplifier, Rail to Rail I/O, 1 Amplifier, 5 MHz, 2 V/µs; 3D_Mechanical_Footprint_File: sot23-5; Farnell: 2511012; HEIGHT: 1.45MM; MFG_NAME01: Maxim; Manufacturer: Maxim; ROHS: Yes; Temp Range: -40C to 125C; VOLTAGE: 2.7-6.5V
C13-C15 C17 = CAPACITOR__0: CAP CER 0.1UF 25V X7R 0402; CLASS: DISCRETE; FPLIST: CC0402_25,CC0402_HD,0402_CC; HEIGHT: 0.55MM; MFG_NAME01: TDK; MFG_PN01: CGA2B3X7R1E104K050BB; Manufacturer: TDK; Manufacturer PN: CGA2B3X7R1E104K050BB; Package Size: 0402; Package Type: SMD; ROHS: Yes; TOLERANCE: 10%; VOLTAGE: 25V
C16 = CAPACITOR__0: CAP CER 0.1UF 25V X7R 0402; CLASS: DISCRETE; FPLIST: CC0402_25,CC0402_HD,0402_CC; HEIGHT: 0.55MM; MFG_NAME01: TDK; MFG_PN01: CGA2B3X7R1E104K050BB; Manufacturer: TDK; Manufacturer PN: CGA2B3X7R1E104K050BB; PUISS/VOLT: 25V; Package Size: 0402; Package Type: SMD; TOLERANCE: 10%; TYPE: 0402; VOLTAGE: 25V
C21 C25 C87 = CAP_NP: SMD Multilayer Ceramic Capacitor, 4.7 µF, 16 V, ± 10%, X5R; CAD_APPROVED: Yes; FPLIST: CC0603_OV,CC0603; Farnell: 3581438; HEIGHT: 1MM; MFG_NAME01: MURATA; MFG_PN01: GRT188R61C475KE13D; Manufacturer: MURATA; Manufacturer PN: GRT188R61C475KE13D; Package Size: 0603; ROHS: Yes; TYPE: 0603; Tolerance: 10%; VOLTAGE: 16V
J13 = CONN_HDR_7X2: SILK: SENSOR SELECT
R25 R26 R229 = RES: RES MF 10K 1/10W 5% 0603; AGILE_PN: 470-75410; CAD_APPROVED: Yes; FPLIST: RC0603_OV,RC0603,0603_CC; HEIGHT: 0.55MM; MFG_NAME01: BOURNS; MFG_PN01: CR0603-JW-103ELF; Manufacturer: BOURNS; Manufacturer PN: CR0603-JW-103ELF; ROHS: Yes; Temp Range: –55 °C to +155 °C; Tolerance: 5%
R27 = RES: RES MF 1.0K 1/16W 5% 0402; AGILE_PN: 470-82125; CAD_APPROVED: Yes; FPLIST: RC0402_25,RC0402_HD,RC0402_X2,0402_CC; HEIGHT: 0.4MM; MFG_NAME01: NIC COMPONENTS CORP; MFG_PN01: NRCL04J102TRF; Manufacturer: NIC COMPONENTS CORP; Manufacturer PN: NRCL04J102TRF; ROHS: Yes; Temp Range: -55°C to +155°C; Temp_Range: -55°C to +155°C; Tolerance: 5%
U6 = FXLS8974CF: Distributor: Digikey; Manufacturer: NXP
U7 = FXPQ3115BV: Pressure Sensor, Absolute, 20 kPa, 110 kPa, 1.95 V, 3.6 V; Distributor: Digikey; Distributor PN: 568-13618-1-ND; Farnell: 3128735; Manufacturer: NXP
U8 = TMP117_0: SENSOR TEMP; Distributor: Digikey; Distributor PN: 296-52215-1-ND; Manufacturer: Texas Instruments; Manufacturer PN: TMP117MAIDRVT
U29 = 74AUP1G09GW,125: Logic IC, AND Gate, Single, 2 Inputs, 5 Pins, TSSOP, 74AUP1G09; Distributor PN: 1727-4492-1-ND; Farnell: 2164673; Manufacturer: Nexperia
C18-C20 C24 = CAP_NP: SMD Multilayer Ceramic Capacitor, 10 µF, 10 V, 0603, ± 20%, X5R; CAD_APPROVED: Yes; FPLIST: CC0603_OV,CC0603; Farnell: 2113070; HEIGHT: 1MM; MFG_NAME01: Taiyo Yuden; MFG_PN01: LMK107BBJ106MALT; Manufacturer: Taiyo Yuden; Manufacturer PN: LMK107BBJ106MALT; Package Size: 0603; ROHS: Yes; Tolerance: 20%; VOLTAGE: 10V
J14 J15 J17 J18 J20 J21 = CONN_HDR_8X1: CON 1X8 SKT SHRD TH 100MIL SP 335H AU 126L; AGILE_PN: 210-78679; CAD_APPROVED: Yes; HEIGHT: 8.75MM; MFG_NAME01: SULLINS ELECTRONICS CORP; MFG_PN01: PPPC081LFBN-RC; Manufacturer: SULLINS ELECTRONICS CORP; Manufacturer PN: PPPC081LFBN-RC; ROHS: Yes
J16 J22 = CONN_HDR_2X1: ROHS: Yes
J23 J26 = CONN_HDR_8X1: PCB Receptacle, Board-to-Board, 2.54 mm, 1 Rows, 8 Contacts, Through Hole Mount, M20; AGILE_PN: 210-78679; CAD_APPROVED: Yes; Farnell: 3225927; HEIGHT: 8.75MM; MFG_NAME01: Harwin; MFG_PN01: M20-7820842; Manufacturer: Harwin; Manufacturer PN: M20-7820842; ROHS: Yes
J24 = Con_10x1: PCB Receptacle, Board-to-Board, 2.54 mm, 1 Rows, 10 Contacts, Through Hole Mount, M20; Farnell: 3225928; MFG_NAME01: Harwin; MFG_PN01: M20-7821042; Manufacturer: Harwin; Manufacturer PN: M20-7821042
J25 = Con_6x1: PCB Receptacle, Board-to-Board, 2.54 mm, 1 Rows, 6 Contacts, Through Hole Mount, M20; Farnell: 3225924; MFG_NAME01: Harwin; MFG_PN01: M20-7820642; Manufacturer: Harwin; Manufacturer PN: M20-7820642
JP37 = Solderjumper: ASSY_OPT: DNP; Assembly Option: DNP
R29 R30 R37 = RES: RES MF ZERO OHM 1/16W -- AEC-Q200 0402; AGILE_PN: 470-81849; CAD_APPROVED: Yes; FPLIST: RC0402_25,RC0402_HD,0402_CC; HEIGHT: 0.45 MM; MFG_NAME01: STACKPOLE ELECTRONICS; MFG_PN01: RMCF0402ZT0R00; Manufacturer: STACKPOLE ELECTRONICS; Manufacturer PN: RMCF0402ZT0R00; ROHS: Yes
C22 C23 C26-C30 C36 C39 C42 C44 C48 C49 C83 = CAP_NP: CAP CER 0.1UF 25V X7R 0402; FPLIST: CC0402_25,CC0402_HD,0402_CC; HEIGHT: 0.55MM; MFG_NAME01: TDK; MFG_PN01: CGA2B3X7R1E104K050BB; Manufacturer: TDK; Manufacturer PN: CGA2B3X7R1E104K050BB; Package Size: 0402; Package Type: SMD; ROHS: Yes; TYPE: 0402; Tolerance: 10%; VOLTAGE: 25V
D8 D9 D11-D14 = LED: LED GRN SGL 25MA 0603; CAD_APPROVED: Yes; Farnell: 2099223; HEIGHT: 0.85MM; MFG_NAME01: KINGBRIGHT; MFG_PN01: KPT-1608SGC; Manufacturer: KINGBRIGHT; Manufacturer PN: KPT-1608SGC; ROHS: Yes
D10 = LED: LED RED SGL 20MA SMT; CAD_APPROVED: Yes; Farnell: 2630066; HEIGHT: 0.67MM; MFG_NAME01: OSRAM; MFG_PN01: LS L29K-H1J2-1; Manufacturer: OSRAM; Manufacturer PN: LS L29K-H1J2-1; ROHS: Yes; VOLTAGE: 1.8V
J27 = CONN_HDR_3X2: ASSY_OPT: DNP; Assembly Option: DNP
J28 = CONN_HDR_2X1: SILK: SPI / I2C
J29 = CONN_HDR_2X1: SILK: VCOM
J30 = CONN_HDR_2X1: SILK: SWD
J31 = CONN_HDR_5X2: Pin Header, Wire-to-Board, 1.27 mm, 2 Rows, 10 Contacts, Through Hole, SHF Series; ASSY_OPT: DNP; Farnell: 2308450; HEIGHT: 5.33mm; Jumper (Default): OPEN; MFG_NAME01: Samtec; Manufacturer: Samtec; ROHS: Yes; Temp Range: -55DegC to +105DegC; Temp_Range: -55DegC to +105DegC; Datasheet: https://www.farnell.com/datasheets/1927736.pdf
R38 = RES: RES MF 200K 1/10W 1% AEC-Q200 0603; AGILE_PN: 470-76381; CAD_APPROVED: Yes; FPLIST: RC0603_OV,RC0603,0603_CC; HEIGHT: 0.55 MM; MFG_NAME01: KOA SPEER; MFG_PN01: RK73H1JTTD2003F; Manufacturer: KOA SPEER; Manufacturer PN: RK73H1JTTD2003F; ROHS: Yes; Temp Range: -55C to +155C; Tolerance: 1%
R39 R52 R53 R55 R60 = RES: RES MF 100K 1/16W 1% 0402; AGILE_PN: 470-76240; CAD_APPROVED: Yes; FPLIST: RC0402_25,RC0402_HD,0402_CC; HEIGHT: 0.4MM; MFG_NAME01: NIC COMPONENTS CORP; MFG_PN01: NRCL04F1003TRF; Manufacturer: NIC COMPONENTS CORP; Manufacturer PN: NRCL04F1003TRF; ROHS: Yes; Tolerance: 1%
R40 R57 = RES: RES MF ZERO OHM 1/10W -- 0603; AGILE_PN: 470-80866; CAD_APPROVED: Yes; FPLIST: RC0603_OV,RC0603,R603-X2,0603_CC; HEIGHT: 0.6MM; MFG_NAME01: YAGEO AMERICA; MFG_PN01: RC0603FR-070RL; Manufacturer: YAGEO AMERICA; Manufacturer PN: RC0603FR-070RL; ROHS: Yes; Temp Range: –55 °C to +155 °C
R41 = RES: RES MF ZERO OHM 1/10W -- 0603; AGILE_PN: 470-80866; ASSY_OPT: DNP; Assembly Option: DNP; CAD_APPROVED: Yes; FPLIST: RC0603_OV,RC0603,R603-X2,0603_CC; HEIGHT: 0.6MM; MFG_NAME01: YAGEO AMERICA; MFG_PN01: RC0603FR-070RL; Manufacturer: YAGEO AMERICA; Manufacturer PN: RC0603FR-070RL; ROHS: Yes; Temp Range: –55 °C to +155 °C
R42 R43 = RES: RES MF 2.0K 1/10W 5% 0603; AGILE_PN: 470-75408; CAD_APPROVED: Yes; FPLIST: RC0603_OV,RC0603,0603_CC; HEIGHT: 0.55MM; MFG_NAME01: BOURNS; MFG_PN01: CR0603-JW-202ELF; Manufacturer: BOURNS; Manufacturer PN: CR0603-JW-202ELF; ROHS: Yes; Tolerance: 5%; VOLTAGE: 1/10W
R44 R45 R54 R56 R58 R59 R61 = RES: RES 510 OHMS 1/16W 5% RC0402 ROHS; AGILE_PN: 470-76237; CAD_APPROVED: Yes; FPLIST: RC0402_25,RC0402_HD,0402_CC; HEIGHT: 0.4 MM; MFG_NAME01: YAGEO AMERICA; MFG_PN01: RC0402JR-07510RL; Manufacturer: YAGEO AMERICA; Manufacturer PN: RC0402JR-07510RL; ROHS: Yes; Temp_Range: -55C to +155C
R46 R49-R51 R62 = RES: RES MF 1K 1/16W 0.5% 0402; AGILE_PN: 470-80057; CAD_APPROVED: Yes; FPLIST: RC0402_25,RC0402_HD,0402_CC; HEIGHT: 0.4MM; MFG_NAME01: PANASONIC; MFG_PN01: ERA2AED102X; Manufacturer: PANASONIC; Manufacturer PN: ERA2AED102X; ROHS: Yes; Tolerance: 0.5%
R47 R48 = RES: RES MF 1K 1/16W 0.5% 0402; AGILE_PN: 470-80057; ASSY_OPT: DNP; Assembly Option: DNP; CAD_APPROVED: Yes; FPLIST: RC0402_25,RC0402_HD,0402_CC; HEIGHT: 0.4MM; MFG_NAME01: PANASONIC; MFG_PN01: ERA2AED102X; Manufacturer: PANASONIC; Manufacturer PN: ERA2AED102X; ROHS: Yes; Tolerance: 0.5%
U9 = LPC55S69JB_HLQFP100: IC MCU 32BIT ARM FLASH 640KB SRAM 320KB 1.8-3.6V HLQFP100; AGILE_PN: 344-02385; CAD_APPROVED: Yes; HEIGHT: 1.6MM; MFG_NAME01: NXP SEMICONDUCTORS; Manufacturer: NXP SEMICONDUCTORS; ROHS: Yes; Temp Range: -40C to +105C; VOLTAGE: 1.8-3.6V
BD1 = INDUCTOR_0: FERRITE BEAD 470 OHM 0603 1LN; Farnell: 3471128; MFG_NAME01: Murata Electronics North America; MFG_PN01: BLM18KG471SZ1D; Manufacturer: Murata Electronics North America; Manufacturer PN: BLM18KG471SZ1D; TYPE: 0603; Datasheet: http://media.digikey.com/pdf/Data%20Sheets/Murata%20PDFs/BLM18yyyyyyN1x.pdf
C35 C40 C41 = CAP_NP: CAP CER 47pF 50V 5% C0G/NPO 0402; AGILE_PN: 150-79357; CAD_APPROVED: Yes; FPLIST: CC0402_25,CC0402_HD,0402_CC; HEIGHT: 0.9MM; MFG_NAME01: TDK; MFG_PN01: 04025A470JAT2A; Manufacturer: TDK; Manufacturer PN: 04025A470JAT2A; Package Size: 0402; Package Type: Reel; ROHS: Yes; Tolerance: 5%; VOLTAGE: 50V
C37 C43 = CAP_NP: CAP CER 22uF 10V 20% X5R 0603; AGILE_PN: 150-79530; CAD_APPROVED: Yes; FPLIST: CC0603_OV,CC0603; HEIGHT: 1MM; MFG_NAME01: TDK; MFG_PN01: C1608X5R1A226M080AC; Manufacturer: TDK; Manufacturer PN: C1608X5R1A226M080AC; Package Size: 0603; ROHS: Yes; Tolerance: 20%; VOLTAGE: 10V
C38 = CAP_NP: SMD Multilayer Ceramic Capacitor, 10 µF, 10 V, 0603, ± 20%, X5R; AGILE_PN: 150-79516; CAD_APPROVED: Yes; FPLIST: CC0603_OV,CC0603; Farnell: 2113070; HEIGHT: 1MM; MFG_NAME01: Taiyo Yuden; MFG_PN01: LMK107BBJ106MALT; Manufacturer: Taiyo Yuden; Manufacturer PN: LMK107BBJ106MALT; Package Size: 0603; ROHS: Yes; Tolerance: 20%; VOLTAGE: 10V
C46 C47 = CAP_NP: CAP CER 12PF 25V 5% C0G 0402; AGILE_PN: 150-30180; ASSY_OPT: DNP; Assembly Option: DNP; CAD_APPROVED: Yes; FPLIST: CC0402_25,CC0402_HD,0402_CC; HEIGHT: 0.55 MM; MFG_NAME01: KEMET; MFG_PN01: C0402C120J3GAC7867; Manufacturer: KEMET; Manufacturer PN: C0402C120J3GAC7867; ROHS: Yes; Tolerance: 5%
C50 = CAP_NP: CAP CER 1UF 16V X5R 0603; Distributor: Digi-Key; Distributor PN: 490-1536-6-ND; MFG_NAME01: Murata Electronics North America; MFG_PN01: GRM188R61C105KA93D; Manufacturer: Murata Electronics North America; Manufacturer PN: GRM188R61C105KA93D; OrderCode: FARNELL 1907343; PUISS/VOLT: 16V; STUFFING: YES; Type: 0603; Datasheet: http://www.murata.com/~/media/webrenewal/support/library/catalog/products/capacitor/mlcc/c02e.ashx
C51 = CAPACITOR__0: SMD Multilayer Ceramic Capacitor, 4.7 µF, 16 V, ± 10%, X5R; CAD_APPROVED: Yes; CLASS: DISCRETE; FPLIST: CC0603_OV,CC0603; Farnell: 3581438; HEIGHT: 1MM; MFG_NAME01: MURATA; MFG_PN01: GRT188R61C475KE13D; Manufacturer: Murata Electronics North America; Manufacturer PN: GRM188R61A475KE15D; PUISS/VOLT: 10V; Package Size: 0603; TYPE: 0603; VOLTAGE: 16V
C52 = CAPACITOR__0: CAP CER 0.1UF 25V X7R 0402; ASSY_OPT: DNP; Assembly Option: DNP; CLASS: DISCRETE; FPLIST: CC0402_25,CC0402_HD,0402_CC; HEIGHT: 0.55MM; MFG_NAME01: TDK; MFG_PN01: CGA2B3X7R1E104K050BB; Manufacturer: TDK; Manufacturer PN: CGA2B3X7R1E104K050BB; Package Size: 0402; Package Type: SMD; ROHS: Yes; TOLERANCE: 10%; TYPE: 0402; VOLTAGE: 25V
C53 = CAP_NP: CAP CER 2.2UF 10V 10% X5R 0402; AGILE_PN: 150-79475; CAD_APPROVED: Yes; FPLIST: CC0402_25,CC0402_HD,0402_CC; HEIGHT: 0.56MM; MFG_NAME01: AVX; MFG_PN01: 0402ZD225KAT2A; Manufacturer: AVX; Manufacturer PN: 0402ZD225KAT2A; Package Size: 0402; ROHS: Yes; Tolerance: 10%; VOLTAGE: 10V
D16 = LED: LED BLUE SGL 25MA 0603; CAD_APPROVED: Yes; Farnell: 2217972; HEIGHT: 0.85MM; MFG_NAME01: KINGBRIGHT; MFG_PN01: KPT-1608QBC-D; Manufacturer: KINGBRIGHT; Manufacturer PN: KPT-1608QBC-D; ROHS: Yes
D18 = DIODE_SCHOTTKY_2: Schottky Rectifier, 40 V, 1 A, Single, SOD-123, 2 Pins, 640 mV; Farnell: 2760412; MFG_NAME01: NEXPERIA; Manufacturer: NEXPERIA
D19 = DIODE_SCHOTTKY_3: Schottky Rectifier, 40 V, 1 A, Single, SOD-123, 2 Pins, 640 mV; Farnell: 2760412; MFG_NAME01: NEXPERIA; Manufacturer: NEXPERIA
J33 = USB_MINI_B_SKT_3: USB Connector, Micro USB Type AB, USB 2.0, Receptacle, 5 Ways, Surface Mount, Right Angle; AGILE_PN: 211-79256; CAD_APPROVED: Yes; Distributor: Digi-Key; Farnell: 2470832; HEIGHT: 4.1 MM; Manufacturer: WURTH ELEKTRONIK; Manufacturer PN: 629105150921; ROHS: Yes; SILK: MCULink; Datasheet: http://katalog.we-online.de/datasheet/629105150921.pdf
J34 = USB_MINI_B_SKT_3: USB Connector, Micro USB Type AB, USB 2.0, Receptacle, 5 Ways, Surface Mount, Right Angle; AGILE_PN: 211-79256; CAD_APPROVED: Yes; Distributor: Digi-Key; Farnell: 2470832; HEIGHT: 4.1 MM; Manufacturer: WURTH ELEKTRONIK; Manufacturer PN: 629105150921; ROHS: Yes; SILK: USB_PWR; Datasheet: http://katalog.we-online.de/datasheet/629105150921.pdf
L1-L3 = INDUCTOR: IND FER BEAD 600OHM@100MHz 1A 25% 0603; AGILE_PN: 180-78469; CAD_APPROVED: Yes; HEIGHT: 1MM; MFG_NAME01: WURTH ELEKTRONIK EISOS GMBH & CO. KG (ELECTRONIC & ELECTROMEHANICAL COMP); MFG_PN01: 742792651; Manufacturer: WURTH ELEKTRONIK EISOS GMBH & CO. KG (ELECTRONIC & ELECTROMEHANICAL COMP); Manufacturer PN: 742792651; ROHS: Yes
L4 = INDUCTOR: IND WW PWR 4.7UH@40MHZ 3A 30% SMT; AGILE_PN: 180-78209; CAD_APPROVED: Yes; HEIGHT: 2.2MM; MFG_NAME01: MURATA; MFG_PN01: LQH5BPN4R7NT0; Manufacturer: MURATA; Manufacturer PN: LQH5BPN4R7NT0; ROHS: Yes
L5 = BEAD: IND FER BEAD 330OHM@100MHZ 1.7A 0603; AGILE_PN: 180-78156; CAD_APPROVED: Yes; FPLIST: ind_1608,0603_CC; HEIGHT: 0.95MM; MFG_NAME01: TDK; MFG_PN01: MPZ1608S331A; Manufacturer: TDK; Manufacturer PN: MPZ1608S331A; PART_TYPE: FERRITE\BEAD; ROHS: Yes; Tolerance: 25%
Q12 = MOSFET_P_0: TRAN PMOS PWR 3.9A 20V SOT23; AGILE_PN: 480-78071; CAD_APPROVED: Yes; Farnell: 3440080; HEIGHT: 1.1 MM; MFG_NAME01: NEXPERIA; Manufacturer: NEXPERIA; ROHS: Yes
R63 R161 = RES: RES MF 10K 1/16W 1% 0402; AGILE_PN: 470-80452; CAD_APPROVED: Yes; FPLIST: RC0402_25,RC0402_HD,0402_CC; HEIGHT: 0.40 MM; MFG_NAME01: NIC COMPONENTS CORP; MFG_PN01: NRCL04F1002TRF; Manufacturer: NIC COMPONENTS CORP; Manufacturer PN: NRCL04F1002TRF; ROHS: Yes; Tolerance: 1%
R64 = RES: RES MF 20K 1/10W 0.1% 0402; ASSY_OPT: DNP; Assembly Option: DNP; CAD_APPROVED: Yes; FPLIST: RC0402_25,RC0402_HD,0402_CC; HEIGHT: 0.4MM; ROHS: Yes; Temp Range: -55°C ~ 125°C; Tolerance: 0.1%
R65 = RES: RES 510 OHMS 1/16W 5% RC0402 ROHS; CAD_APPROVED: Yes; FPLIST: RC0402_25,RC0402_HD,0402_CC; HEIGHT: 0.4 MM; ROHS: Yes; Temp_Range: -55C to +155C
R162 = RES: RES MF 3k3 1/10W 5% 0402; CAD_APPROVED: Yes; FPLIST: RC0402_25,RC0402_HD,0402_CC; HEIGHT: 0.55MM; ROHS: Yes; Temp Range: –55 °C to +155 °C; Tolerance: 5%
U10 = LM4040_SOT23_0: IC VOLT REF SHUNT 3V 0.5% SOT23-3; AGILE_PN: 315-80874; CAD_APPROVED: Yes; Farnell: 3483099; HEIGHT: 1.13MM; MFG_NAME01: DIODES; Manufacturer: DIODES; ROHS: Yes; VOLTAGE: 3V
U11 = TPS76930_1: IC REG LDO 3.3V 0.2A 5SOT; Distributor: Digi-Key; Farnell: 1331509; Manufacturer: Texas Instruments; STUFFING: YES; Supplier: Digikey; Datasheet: http://www.ti.com/lit/ds/slvsa00e/slvsa00e.pdf
U12 = RCLAMP1654P_NEW: DIODE TVS ARRAY 3 5.5V SLP1616P6; AGILE_PN: 480-78843; CAD_APPROVED: Yes; Distributor: Digi-Key; Distributor PN: RCLAMP0854P.TCTCT-ND; HEIGHT: 0.65MM; MFG_NAME01: SEMTECH CORP; Manufacturer: SEMTECH CORP; ROHS: Yes; VOLTAGE: 5.5V
Y1 = XTAL_0: Crystal, 16 MHz, SMD, 3.2mm x 2.5mm, 20 ppm, 8 pF, 10 ppm, CFPX-180; AGILE_PN: 230-78366; CAD_APPROVED: Yes; Farnell: 3583497; Frequency Stability: 150ppm; Frequency Tolerance: 50ppm; HEIGHT: 0.037" (0.95mm); MFG_NAME01: IQD FREQUENCY PRODUCTS; MFG_PN01: LFXTAL082071; Manufacturer: IQD FREQUENCY PRODUCTS; Manufacturer PN: LFXTAL082071; Package Size: 0.126" L x 0.098" W (3.20mm x 2.50mm); ROHS: Yes; Temp Range: -40 to 150 °C

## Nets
1V5: J1.7(A4) J2.5(A3) J3.3 J6.2 J7.1
1V5_SNS+: J1.5(A3) J5.2(B1) J5.4(B2) J6.1
1V5_SNS-: J2.7(A4) J7.2 J8.1
3V0: J1.3(A2) J2.1(A1) J3.1 J9.1 J10.1 R3.1 R9.1
3V0_SNS+: J1.1(A1) J4.1(A1) J4.3(A2) J4.5(A3) J10.2
3V0_SNS-: J2.3(A2) J8.2 J9.2
3V3: C23.1 C38.1 C51.1 J31.1(A1) L1.1 L2.1 L3.1 R44.1 R45.1 R52.1 R53.1 R54.1 R55.1 R56.1 R58.1 R59.1 R61.1 U11.5(OUT) ; also on sheet 7 8 9
+3V3_1V8_ARD: C21.1 J22.2 J23.2 J23.4 J24.8
GND: BAT2.1(-) BAT3.2(-) C1.2 C2.2 C3.2 C4.2 C5.2 C6.1 C7.2 C8.2 C9.2 C10.2 C11.2 C12.2 C13.1 C14.1 C15.1 C16.1 C17.1 C18.2 C19.2 C20.2 C21.2 C22.2 C23.2 C24.2 C25.2 C26.2 C27.2 C28.2 C29.2 C30.2 C31.2 C32.2 C33.2 C34.2 C35.2 C36.2 C37.2 C38.2 C39.2 C40.2 C41.2 C42.2 C43.2 C44.2 C45.2 C46.2 C47.2 C48.2 C49.2 C50.1 C51.2 C52.2 C53.2 C87.2 D4.A D5.A D6.A D7.A D16.C(CATHODE) FIX1.1 FIX2.1 FIX3.1 FIX4.1 J4.7(A4) J4.8(B4) J5.5(A3) J5.6(B3) J8.4 J8.6 J8.8 J8.12 J8.14 J11.3(A2) J11.5(A3) J11.9(A5) J12.6 J12.7 J14.8 J15.8 J17.8 J18.8 J20.8 J21.8 J23.6 J23.7 J24.7 J28.2 J29.2 J30.2 J31.3(A2) J31.5(A3) J31.9(A5) J32.2 J33.5(GND1) J33.F1(SHLD1) J33.F2(SHLD2) J33.F3(SHLD3) J33.F4(SHLD4) J33.F5(SHLD5) J33.F6(SHLD6) J34.5(GND1) J34.F1(SHLD1) J34.F2(SHLD2) J34.F3(SHLD3) J34.F4(SHLD4) J34.F5(SHLD5) J34.F6(SHLD6) J37.2 Q1.S(SOURCE) Q2.S(SOURCE) R1.3 R2.3 R14.2 R18.2 R20.1 R24.1 R39.2 R41.1 R43.2 R46.2 R47.2 R48.2 R49.2 R50.2 R51.2 R60.2 R64.2 R162.2 SW1.2 SW1.4 SW2.2 SW2.4 SW3.2 SW3.4 SW4.2 SW4.4 U1.2(GND) U2.4(GND) U2.5(MODE) U3.2(GND) U4.2(VSS) U6.2(BT_MODE) U6.3(SA0/SPI_MOSI) U6.9(INTF_SEL) U6.10(GND) U7.3(GND) U8.2(GND) U8.4(ADD0) U9.18(VREFN) U9.19(VSSA) U9.33(USB1_VSS_2) U9.37(USB1_VSS_1) U9.46(VSS_DCDC1) U9.47(VSS_DCDC2) U9.52(XTAL32K_P) U9.99(USB0_VSS) U9.101(EPAD) U10.A(ANODE) U10.NC(ANODE/NC) U11.2(GND) U12.7(GND) U29.3(GND) Y1.2 Y1.4 ; also on sheet 7 8 9
VBAT_DCDC/VBAT_PMU: C35.1 C36.1 C37.1 L2.2 U9.49(VBAT_DCDC_1) U9.50(VBAT_DCDC_2) U9.51(VBAT__PMU)
VBUS: BD1.2 C50.2 D18.A(ANODE) R63.1 U11.1(IN) U11.3(EN) ; also on sheet 7
VCC_IF_LINK: R42.1 ; also on sheet 9
VCC_MIKROE: J16.2 R29.1 R30.1 R37.1
ADC0_CH1_CURR: U9.14(PIO0_16/ADC0_8) U9.57(PIO1_14/ACMP0_D) ; also on sheet 7
ADC1_CH1_V: U9.20(PIO0_23/ADC0_0) ; also on sheet 7
ARD_D2: J26.3 R125.1
ARD_D18: J25.5 R126.2
ARD_D19: J25.6 R127.2
ARD_IIC_SCK: J24.10 R116.1
ARD_IIC_SDA: J24.9 R118.1
ARD_RxD: J26.1 R124.1
ARD_SPI_LIFO: J24.5 R120.1
ARD_SPI_LOFI: J24.4 R121.1
ARD_SPI_SCK: J24.6 R119.1
ARD_SPI_SS: J24.3 R122.1
ARD_TxD: J26.2 R123.1
BRG_I2C0_SCL: U9.76(PIO0_21) ; also on sheet 8
BRG_I2C0_SDA: U9.86(PIO0_4/TMS) ; also on sheet 8
BRG_SPI1_MISO: U9.62(PIO1_3) ; also on sheet 8
BRG_SPI1_MOSI: U9.60(PIO0_26) ; also on sheet 8
BRG_SPI1_SCLK: U9.61(PIO1_2) ; also on sheet 8
BRG_SPI1_SSEL: U9.74(PIO0_20) ; also on sheet 8
CTRL_CAL_DISC: U9.3(PIO1_24) ; also on sheet 7
CTRL_CAL_R1: U9.41(PIO1_22) ; also on sheet 7
CTRL_CAL_R2: U9.42(PIO1_23) ; also on sheet 7
CTRL_HIGH_CURR: U9.22(PIO0_15/ADC0_2) U9.94(PIO0_30) ; also on sheet 7
CTRL_HIGH_CURR_DIS: U9.92(PIO0_29) ; also on sheet 7
CTRL_HIGH_CURR_EN: U9.8(PIO0_17) ; also on sheet 7
CURR_RANGE_SET: R38.2 R39.1 U9.24(PIO1_8/ADC0_4)
CURR_SNS+: J1.2(B1) J1.4(B2) J1.6(B3) J1.8(B4) ; also on sheet 7
CURR_SNS-: J2.2(B1) J2.4(B2) J2.6(B3) J2.8(B4) ; also on sheet 7
DBGIF_DETECT: U9.78(PIO0_22) ; also on sheet 9
DBGIF_ISP0_CTRL: U9.72(PIO0_14) ; also on sheet 8
DBGIF_RESET: U9.90(PIO0_19) ; also on sheet 9
DBGIF_RESET_TXEN: U9.71(PIO0_13) ; also on sheet 9
DBGIF_TCK_SWCLK: U9.54(PIO0_0/ACMP0_A) ; also on sheet 9
DBGIF_TDO_SWO: U9.83(PIO0_3/TCK) ; also on sheet 9
DBGIF_TMS_SWDIO: U9.81(PIO0_2/TRST) ; also on sheet 9
DBGIF_TMS_SWDIO_TXEN: U9.66(PIO0_28/WAKEUP) ; also on sheet 9
DBGIF_VREF: C22.1 R42.2 R43.1 U9.23(PIO0_31/ADC0_3)
FUNC: D12.C(CATHODE) U9.87(PIO1_16)
HW_VER_0: R47.1 U9.85(PIO1_27)
HW_VER_1: R48.1 U9.73(PIO1_28)
HW_VER_2: J28.1 U9.65(PIO1_30/WAKEUP) ; also on sheet 8
HW_VER_3: R49.1 U9.1(PIO1_4)
HW_VER_4: R50.1 U9.31(PIO1_5)
HW_VER_5: R51.1 U9.5(PIO1_6)
HW_VER_6: J29.1 U9.56(PIO0_18/ACMP0_C) ; also on sheet 8
HW_VER_7: J30.1 U9.27(PIO0) ; also on sheet 9
HW_VER_8: R46.1 U9.55(PIO0_9/ACMP0_B)
LED_NRG: D14.C(CATHODE) U9.64(PIO1_18/WAKUP)
LED_SIO: D13.C(CATHODE) U9.43(PIO1_17)
LED_SWO_ACT: D9.C(CATHODE) U9.2(PIO1_13)
LED_USB_COMM: D8.C(CATHODE) U9.67(PIO1_12)
LED_VCOM_ACT: D11.C(CATHODE) U9.82(PIO1_15)
LPC_P1_7-MCULINK: J27.6(B3) U9.9(PIO1_7)
LPC_P1_20-MCULINK: J27.5(A3) U9.4(PIO1_20)
LPC_P1_21-MCULINK: J27.2(B1) U9.30(PIO1_21)
LPC_P1_31-MCULINK: J27.4(B2) U9.91(PIO1_31)
LPC_PIO0_5-ISP_EN-LED_SWD_ACT: D10.C(CATHODE) J32.1 R55.2 R57.1 U9.88(PIO0_5/TDI)
LPC_PIO0_10-SWO: J31.6(B3) R52.2 U9.21(PIO0_10/ADC0_1)
LPC_PIO0_11-SWDCLK: J31.4(B2) R60.1 U9.13(PIO0_11/ADC0_9)
LPC_PIO0_12-SWDIO: J31.2(B1) R53.2 U9.12(PIO0_12/ADC0_10)
MCU_LINK_3V3: C24.1 C25.1 C26.1 C27.1 C28.1 C29.1 C30.1 C31.1 C32.1 C33.1 C34.1 C48.1 C49.1 L1.2 R38.1 U9.15(VDD_1) U9.25(VDD_2) U9.38(USB1_3V3) U9.44(VDD_3) U9.63(VDD_4) U9.69(VDD_5) U9.75(VDD_6) U9.84(VDD_7) U9.95(VDD_8) U9.96(USB0_3V3) U9.100(VDD_9)
MCU_LINK_N_16MHz: C47.1 U9.28(XTAL32M_N) Y1.1
MCU_LINK_P_16MHz: C46.1 U9.29(XTAL32M_P) Y1.3
MCU_LINK_RST: J31.10(B5) U9.32(RESETN)
MCU_LNK_RX: U9.70(PIO0_24) ; also on sheet 8
MCU_LNK_TX: U9.79(PIO0_25) ; also on sheet 8
MCULink_VDDA: C39.1 C40.1 L3.2 R62.1 U9.16(VDDA)
NFC_3V0: J4.2(B1) R154.2 R155.2
P1_1-MCULINK: J27.1(A1) U9.59(PIO1_1/WAKEUP) ; also on sheet 8
P1_9-MCULINK: J27.3(A2) U9.10(PIO1_9/ADC0_12) ; also on sheet 8
PIO0_0-FC0_CTS_SDA_SSEL0: J12.10 R122.2 R149.1 ; also on sheet 8
PIO0_1: J12.3 J13.3(A2) R125.2 R156.2
PIO0_2-FC0_RXD_SDA_MOSI: J12.1 J13.7(A4) J19.10(B5) R118.2 R121.2 R124.2 R126.1 R152.1 R157.2 R160.2 ; also on sheet 8
PIO0_3-FC0_TXD_SCL_MISO: J12.18 J13.11(A6) J19.12(B6) R116.2 R120.2 R123.2 R127.1 R151.1 R158.2 R159.2 ; also on sheet 8
PIO0_4-FC0_SCK: J12.2 R119.2 R150.1 ; also on sheet 8
PIO0_5-FC2_CTS_SDA_SSEL0: J12.11 R142.1
PIO0_6-FC2_RXD_SDA_MOSI-SPIFI_IO0: J12.13 J19.2(B1) R130.2 R133.2 R145.1
PIO0_7-FC2_TXD_SCL_MISO-SPIFI_IO1: J12.14 J19.4(B2) R131.2 R132.2 R144.1
PIO0_8-SPIFI_IO2: J12.19 R128.2
PIO0_9-SPIFI_IO3: J12.20 R129.2
PIO0_10-FC2_SCK: J12.12 R143.1
PIO0_11-SWDCLK: D6.C J8.16 J11.4(B2) R24.2 ; also on sheet 9
PIO0_12-SWDIO: D7.C J8.18 J11.2(B1) R23.1 ; also on sheet 9
PIO0_13-FC1_RXD_SDA_MOSI: J12.5 J13.9(A5) J19.6(B3) R134.2 R135.2 R141.1 ; also on sheet 8
PIO0_14-FC1_TXD_SCL_MISO: J12.4 J13.13(A7) J19.8(B4) R136.2 R137.2 R140.1 ; also on sheet 8
PIO0_15-FC1_CTS_SDA_SSEL0: J12.15 R138.1
PIO0_16-FC1_SCK: J12.16 R139.1
PIO0_17-SWO: D5.C J11.6(B3) J12.17 R22.1 ; also on sheet 9
PIO0_18-FC2_RXD_SDA_MOSI: J12.8 R21.2 ; also on sheet 8
PIO0_19-FC2_TXD_SCL_MISO: J12.9 Q1.G(GATE) R14.1 ; also on sheet 8
PIO0_20-ISP: J8.17 R15.2 ; also on sheet 8
PIO0_21-WAKEUP: D1.A J8.19 R16.2
PIO0_22: J8.15 J13.5(A3) R153.2
RDM_RESETn: D4.C J8.13 J11.10(B5) R10.2 ; also on sheet 9
RSTn_BOARDS: JP37.1 R11.2 R146.1 R147.1 R148.1
SENSOR_I2C_SCL: J13.12(B6) J13.14(B7) U6.5(SCL/SCLK) U7.8(SCL) U8.1(SCL)
SENSOR_I2C_SDA: J13.8(B4) J13.10(B5) U6.4(SDA/SPI_MOSI/SPI_DATA) U7.7(SDA) U8.6(SDA)
SENSOR_INT: J13.4(B2) R26.2 R163.2 R164.2 R165.2 U29.2(A)
SENSOR_VDD: C14.2 C15.2 C17.2 C87.1 J13.2(B1) R25.1 R26.1 R166.2 R229.1 U6.1(VDD) U7.1(VDD) U7.4(VDDIO) U8.5(V+) U29.5(VCC)
SYS_5V0: C1.1 C4.1 C6.2 C7.1 C83.1 Q12.D(DRAIN) R65.1 U1.1(IN) U1.3(EN) U3.1(IN) U3.3(EN) U4.5(VDD) ; also on sheet 7
USB_1V5: C2.1 J5.1(A1) U1.5(OUT)
USB_3V0: C5.1 J4.4(B2) U3.5(OUT)
USB_DM: J33.2(D-) U9.35(USB1_DM) U12.1(DM)
USB_DP: J33.3(D+) U9.34(USB1_DP) U12.2(DP)
VIO: C3.1 C12.1 J8.3 J8.5 J11.1(A1) J13.1(A1) J16.1 J22.1 Q2.G(GATE) R1.1 R2.1 R5.1 R6.1 R7.1 R8.1 R13.2 R18.1 R19.2 R22.2 R23.2 R31.1 R32.1 R33.1 R34.1 R35.1 R36.1 U2.1(VDD) ; also on sheet 8 9
VREF_MCULINK: C44.1 C45.1 R40.2 R62.2 U9.17(VREFP) U10.C(CATHODE)
N12265657: C18.1 J14.7 R29.2
N12266589: C19.1 J18.7 R30.2
N12275396: J14.2 R148.2
N12275400: J14.3 R149.2
N12275404: J14.4 R150.2
N12275408: J14.5 R151.2
N12275412: J14.6 R152.2
N12276056: J15.1 R155.1
N12276068: J15.2 R156.1
N12276080: J15.3 R157.1
N12276104: J15.4 R158.1
N12276108: J15.5 R159.1
N12276112: J15.6 R160.1
N12276934: J18.2 R146.2
N12276966: J18.3 R138.2
N12276998: J18.4 R139.2
N12277030: J18.5 R140.2
N12277038: J18.6 R141.2
N12277309: J17.1 R154.1
N12277341: J17.2 R153.1
N12277373: J17.3 R135.1
N12277413: J17.4 R136.1
N12277445: J17.5 R137.1
N12277469: J17.6 R134.1
N12278499: J21.1 R128.1
N12278559: J20.2 R147.2
N12278563: J21.2 R129.1
N12278623: J20.3 R142.2
N12278627: J21.3 R130.1
N12278695: J20.4 R143.2
N12278699: J21.4 R131.1
N12278759: J20.5 R144.2
N12278763: J21.5 R132.1
N12278819: J20.6 R145.2
N12278823: J21.6 R133.1
N12278835: C20.1 J20.7 R37.2
N12295606: C16.2 U7.2(CAP)
N12315434: C52.1 U11.4(NC)
N12315580: BD1.1 J33.1(VBUS) U12.6(VBUS)
N12322367: J23.3 JP37.2
N12369229: R63.2 R64.1 U9.36(USB1_VBUS)
N12373644: R40.1 R41.2 U9.58(PIO1_19/ACMPVREF)
N12374436: D8.A(ANODE) R44.2
N12374792: D9.A(ANODE) R45.2
N12374932: D10.A(ANODE) R54.2
N12375074: J31.7(A4) R57.2
N12375164: D11.A(ANODE) R56.2
N12375264: D12.A(ANODE) R58.2
N12375326: D13.A(ANODE) R59.2
N12375380: D14.A(ANODE) R61.2
N12381948: R165.1 U8.3(ALERT)
N12381957: R164.1 U7.6(INT1)
N12382534: R163.1 U6.8(INT1/MOT_DET)
N12393061: C41.1 C42.1 C43.1 L4.2 U9.39(VDD_PMU) U9.45(FB)
N12393117: L4.1 U9.48(LX)
N12422072: BAT3.1(+) BAT3.3(+) J5.3(A2)
N12422390: BAT2.2(+) BAT2.3 J4.6(B3)
N12442192: C9.1 J37.1 R6.2 R15.1 SW2.1 SW2.3
N12442224: C8.1 R5.2 R10.1 R11.1 SW1.1 SW1.3
N12449351: C10.1 R7.2 R16.1 SW3.1 SW3.3
N12450169: C11.1 R8.2 R21.1 SW4.1 SW4.3
N12453362: D1.C U2.6(OUT)
N12454206: R1.2 U2.2(TH-SDA)
N12454210: R2.2 U2.3(ODR-SCL)
N12480389: C53.1 J34.1(VBUS) L5.1
N12480952: D19.A(ANODE) L5.2
N12627127: D16.A(ANODE) R65.2
N12627699: D18.C(CATHODE) D19.C(CATHODE) Q12.S(SOURCE) R161.1
N12627791: C83.2 Q12.G(GATE) R161.2 R162.1
N12648217: J3.2 R12.1 R17.1
N12648225: R12.2 R13.1
N12648461: R17.2 R20.2 U4.3(+IN)
N12648493: R19.1 U4.1(OUT) U4.4(-IN)
N12652986: J19.1(A1) R31.2
N12653032: J19.3(A2) R33.2
N12653078: J19.5(A3) R32.2
N12653124: J19.7(A4) R35.2
N12653170: J19.9(A5) R34.2
N12653192: J19.11(A6) R36.2
N12655772: D2.C(CATHODE) Q1.D(DRAIN)
N12655780: D2.A(ANODE) R3.2
N12655848: D3.C(CATHODE) Q2.D(DRAIN)
N12655856: D3.A(ANODE) R9.2
N12656530: R166.1 U6.7(SPI_CS_B/WAKE_UP)
N12892834: C13.2 R25.2 U29.1(B)
N12892932: R27.2 U29.4(Y)
N12893707: J13.6(B3) R27.1 R229.2

Not connected (* = marked no-connect by the designer): J8 7* 9* 10* 11* 20*; J11 7(A4)* 8(B4)*; J14 1*; J15 7*; J17 7*; J18 1*; J20 1*; J21 7*; J23 1* 5* 8*; J24 1* 2*; J25 1* 2* 3* 4*; J26 4* 5* 6* 7* 8*; J31 8(B4)*; J33 4(ID)*; J34 2(D-) 3(D+) 4(ID)*; U1 4(NC)*; U3 4(NC)*; U6 6(INT2/EXT_TRIG/BOOT_OUT)*; U7 5(INT2)*; U9 6(PIO0_7)* 7(PIO0_1)* 11(PIO1_0/ADC0)* 26(PIO0_8)* 40(PIO1_10)* 53(XTAL32K_N)* 68(PIO1_26)* 77(PIO1_25)* 80(PIO1_29)* 89(PIO0_6/TDO)* 93(PIO1_11)* 97(USB0_DP)* 98(USB0_DM)*; U12 3(USB_ID)* 4(NC1)* 5(NC2)*

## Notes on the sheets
sheet 2
- Magnetic Switch
- VBAT_HV source select
- VBAT_LV source select
- SNS3
- SNS4
- VBAT_LV current
  sense jumpers
- VBAT_HV current
  sense jumpers
- Lithium: CR2032
- SilverOxide: SR927
- Threshold:
     H = High
     L = Medium
     Open = Low
  Sample Rate:
     H = High
     L = Medium
     Open = Low
- RDM Connectors
- User Keys
- LDOs powered by USB
- Current measurement
  selection
- SNS1: 3V Battery
  SNS2: 3V RDM
  SNS3: 1V5 Battery
  SNS4: 1V5 RDM
- SNS1: 3V Battery
  SNS2: 3V RDM
  SNS3: 1V5 Battery
  SNS4: 1V5 RDM
- MCXW23x SWD
- VIO Voltage Select
- USER LEDs
- Buffered VIO
- Max 80mA
- PWR indicator LED
- CAD note:
      Place R12 and R17 side by side
      Place R13 and R19 side by side
- I2C Pull Up resistors
sheet 3
- PIO0_22: Must be low at power-up (at least 5.5us)
           can be used as GPIO later
- Accelerometer
- I²C Adddress: 0x30 / 0x31
- Pressure
- I²C Adddress: 0xC0 / 0xC1
- Temperature
- I²C Adddress: 0x90 / 0x91
sheet 4
- CAD Note: PCB Edge Side
- SHORTING HEADER
  ON BOTTOM LAYER
- AN
  RST
  CS
  SCK
  MISO
  MOSI
  3V3
  GND
- socket board
- PWM
  INT
  RX
  TX
  SCL
  SDA
  5V0
  GND
- FLEXCOMM 0
- CAD Note: PCB Edge Side
- AN
  RST
  CS
  SCK
  MISO
  MOSI
  3V3
  GND
- socket board
- PWM
  INT
  RX
  TX
  SCL
  SDA
  5V0
  GND
- FLEXCOMM 1
- CAD Note: PCB Edge Side - place close to RDM (High speed SPIFI)
- Flash 6 click
- AN
  RST
  CS
  SCK
  MISO
  MOSI
  3V3
  GND
- socket board
- PWM
  INT
  RX
  TX
  SCL
  SDA
  5V0
  GND
- FLEXCOMM 2
- SHORTING HEADER
  ON BOTTOM LAYER
- AREF
- Arduino
sheet 5
- RDM_IO voltage monitor
- MCULINK features
  configuration
- MCULINK LEDs
- MCULINK SWD
  connector
- VCOM
- SWD
- USB Communication
- SWO  activity
- Status / SWD Activity
- PU
- F
- VCOM Activity
- HW_VER0
- USB Power negotiation
- PU
- HW_VER1
- Reserved
- Func
- HW_VER2
- USB SPI/I2C (GPIO) disable
- HW_VER3
- OB/Pro selection
- USB bridge active
- HW_VER4
- Board ID code select
- HW_VER5
- Power mearurement capability
- Open  : Boot from Internal Flash
  Closed: Enable ISP mode (USB1)
- HW_VER6
- VCOM enable/disable
- Current measurement active
- HW_VER7
- SWD enable/disable
- MCULink GPIO
sheet 6
- MCU LINK
- Place 100nF and 47pF caps
  close to Pin 49, 50, 51
- Place C41 & C42
  close to Pin 39
- 3V3 MCULINK LDO
- USB Soft start
- Power LED indicator
